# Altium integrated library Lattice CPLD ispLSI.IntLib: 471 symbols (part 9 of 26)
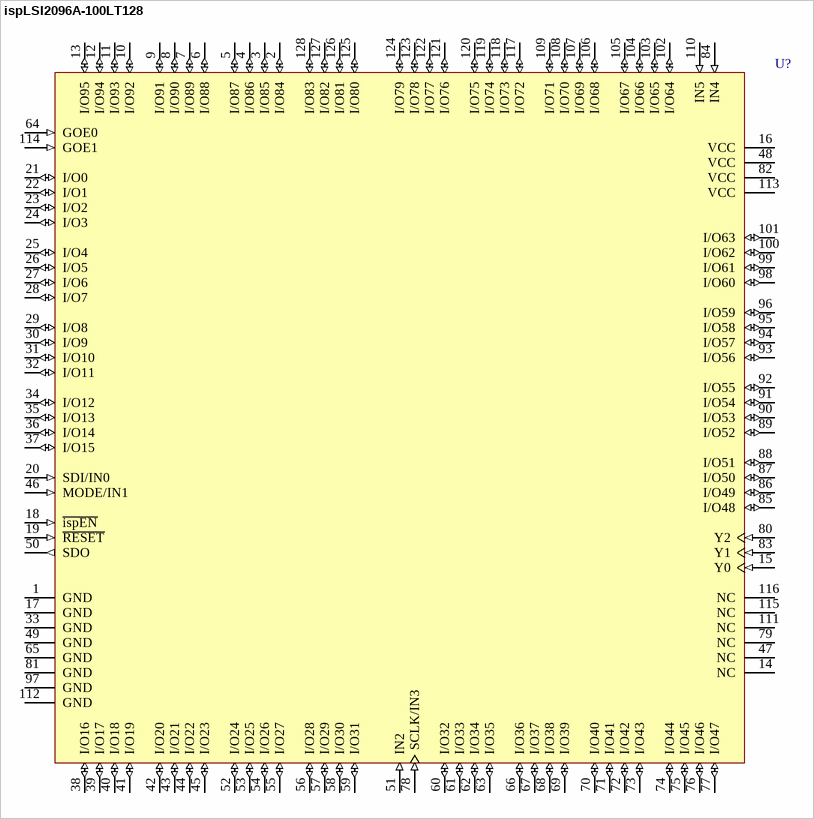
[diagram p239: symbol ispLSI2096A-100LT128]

## ispLSI2096A-100LT128
designator U?
In-System Programmable High-Density PLD; Note: Pins 20, 46 and 78 have dual function capability.
footprint TQFP128_N (Thin QFP, 128-Leads, Body 14x14mm, Pitch 0.4mm, IPC Medium Density)
footprint TQFP128_L (Thin QFP, 128-Leads, Body 14x14mm, Pitch 0.4mm, IPC High Density)
footprint TQFP128_M (Thin QFP, 128-Leads, Body 14x14mm, Pitch 0.4mm, IPC Low Density)
3D model 2096A-TQFP128 (128-Pin Thin Quad Flat Pack 0.4 mm Pitch)
pins: 1 GND (power), 2 I/O84 (io), 3 I/O85 (io), 4 I/O86 (io), 5 I/O87 (io), 6 I/O88 (io), 7 I/O89 (io), 8 I/O90 (io), 9 I/O91 (io), 10 I/O92 (io), 11 I/O93 (io), 12 I/O94 (io), 13 I/O95 (io), 14 NC, 15 Y0 (in), 16 VCC (power), 17 GND (power), 18 ~{ispEN} (in), 19 ~{RESET} (in), 20 SDI/IN0 (in), 21 I/O0 (io), 22 I/O1 (io), 23 I/O2 (io), 24 I/O3 (io), 25 I/O4 (io), 26 I/O5 (io), 27 I/O6 (io), 28 I/O7 (io), 29 I/O8 (io), 30 I/O9 (io), 31 I/O10 (io), 32 I/O11 (io), 33 GND (power), 34 I/O12 (io), 35 I/O13 (io), 36 I/O14 (io), 37 I/O15 (io), 38 I/O16 (io), 39 I/O17 (io), 40 I/O18 (io), 41 I/O19 (io), 42 I/O20 (io), 43 I/O21 (io), 44 I/O22 (io), 45 I/O23 (io), 46 MODE/IN1 (in), 47 NC, 48 VCC (power), 49 GND (power), 50 SDO (out), 51 IN2 (in), 52 I/O24 (io), 53 I/O25 (io), 54 I/O26 (io), 55 I/O27 (io), 56 I/O28 (io), 57 I/O29 (io), 58 I/O30 (io), 59 I/O31 (io), 60 I/O32 (io), 61 I/O33 (io), 62 I/O34 (io), 63 I/O35 (io), 64 GOE0 (in), 65 GND (power), 66 I/O36 (io), 67 I/O37 (io), 68 I/O38 (io), 69 I/O39 (io), 70 I/O40 (io), 71 I/O41 (io), 72 I/O42 (io), 73 I/O43 (io), 74 I/O44 (io), 75 I/O45 (io), 76 I/O46 (io), 77 I/O47 (io), 78 SCLK/IN3 (in), 79 NC, 80 Y2 (in), 81 GND (power), 82 VCC (power), 83 Y1 (in), 84 IN4 (in), 85 I/O48 (io), 86 I/O49 (io), 87 I/O50 (io), 88 I/O51 (io), 89 I/O52 (io), 90 I/O53 (io), 91 I/O54 (io), 92 I/O55 (io), 93 I/O56 (io), 94 I/O57 (io), 95 I/O58 (io), 96 I/O59 (io), 97 GND (power), 98 I/O60 (io), 99 I/O61 (io), 100 I/O62 (io), 101 I/O63 (io), 102 I/O64 (io), 103 I/O65 (io), 104 I/O66 (io), 105 I/O67 (io), 106 I/O68 (io), 107 I/O69 (io), 108 I/O70 (io), 109 I/O71 (io), 110 IN5 (in), 111 NC, 112 GND (power), 113 VCC (power), 114 GOE1 (in), 115 NC, 116 NC, 117 I/O72 (io), 118 I/O73 (io), 119 I/O74 (io), 120 I/O75 (io), 121 I/O76 (io), 122 I/O77 (io), 123 I/O78 (io), 124 I/O79 (io), 125 I/O80 (io), 126 I/O81 (io), 127 I/O82 (io), 128 I/O83 (io)

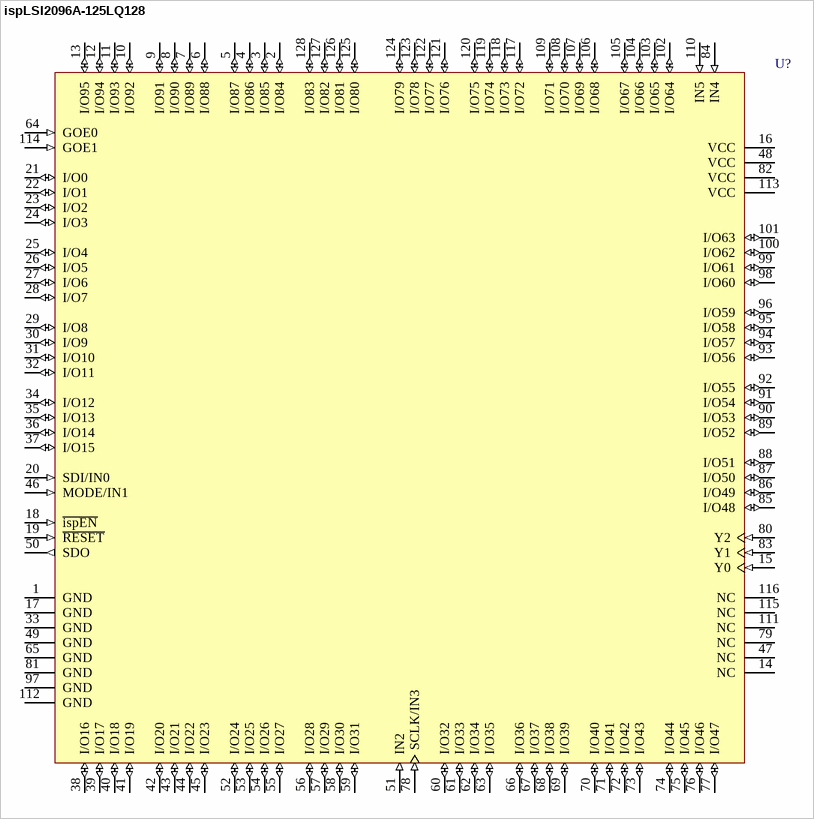
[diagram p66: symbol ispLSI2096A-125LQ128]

## ispLSI2096A-125LQ128
designator U?
In-System Programmable High-Density PLD; Note: Pins 20, 46 and 78 have dual function capability.
footprint PQFP128_N (QFP, 128-Leads, Body 28x28mm, Pitch 0.8mm, IPC Medium Density)
footprint PQFP128_L (QFP, 128-Leads, Body 28x28mm, Pitch 0.8mm, IPC High Density)
footprint PQFP128_M (QFP, 128-Leads, Body 28x28mm, Pitch 0.8mm, IPC Low Density)
3D model 2096A-PQFP128 (128-Pin Quad Flat Pack 0.8 mm Pitch)
pins: 1 GND (power), 2 I/O84 (io), 3 I/O85 (io), 4 I/O86 (io), 5 I/O87 (io), 6 I/O88 (io), 7 I/O89 (io), 8 I/O90 (io), 9 I/O91 (io), 10 I/O92 (io), 11 I/O93 (io), 12 I/O94 (io), 13 I/O95 (io), 14 NC, 15 Y0 (in), 16 VCC (power), 17 GND (power), 18 ~{ispEN} (in), 19 ~{RESET} (in), 20 SDI/IN0 (in), 21 I/O0 (io), 22 I/O1 (io), 23 I/O2 (io), 24 I/O3 (io), 25 I/O4 (io), 26 I/O5 (io), 27 I/O6 (io), 28 I/O7 (io), 29 I/O8 (io), 30 I/O9 (io), 31 I/O10 (io), 32 I/O11 (io), 33 GND (power), 34 I/O12 (io), 35 I/O13 (io), 36 I/O14 (io), 37 I/O15 (io), 38 I/O16 (io), 39 I/O17 (io), 40 I/O18 (io), 41 I/O19 (io), 42 I/O20 (io), 43 I/O21 (io), 44 I/O22 (io), 45 I/O23 (io), 46 MODE/IN1 (in), 47 NC, 48 VCC (power), 49 GND (power), 50 SDO (out), 51 IN2 (in), 52 I/O24 (io), 53 I/O25 (io), 54 I/O26 (io), 55 I/O27 (io), 56 I/O28 (io), 57 I/O29 (io), 58 I/O30 (io), 59 I/O31 (io), 60 I/O32 (io), 61 I/O33 (io), 62 I/O34 (io), 63 I/O35 (io), 64 GOE0 (in), 65 GND (power), 66 I/O36 (io), 67 I/O37 (io), 68 I/O38 (io), 69 I/O39 (io), 70 I/O40 (io), 71 I/O41 (io), 72 I/O42 (io), 73 I/O43 (io), 74 I/O44 (io), 75 I/O45 (io), 76 I/O46 (io), 77 I/O47 (io), 78 SCLK/IN3 (in), 79 NC, 80 Y2 (in), 81 GND (power), 82 VCC (power), 83 Y1 (in), 84 IN4 (in), 85 I/O48 (io), 86 I/O49 (io), 87 I/O50 (io), 88 I/O51 (io), 89 I/O52 (io), 90 I/O53 (io), 91 I/O54 (io), 92 I/O55 (io), 93 I/O56 (io), 94 I/O57 (io), 95 I/O58 (io), 96 I/O59 (io), 97 GND (power), 98 I/O60 (io), 99 I/O61 (io), 100 I/O62 (io), 101 I/O63 (io), 102 I/O64 (io), 103 I/O65 (io), 104 I/O66 (io), 105 I/O67 (io), 106 I/O68 (io), 107 I/O69 (io), 108 I/O70 (io), 109 I/O71 (io), 110 IN5 (in), 111 NC, 112 GND (power), 113 VCC (power), 114 GOE1 (in), 115 NC, 116 NC, 117 I/O72 (io), 118 I/O73 (io), 119 I/O74 (io), 120 I/O75 (io), 121 I/O76 (io), 122 I/O77 (io), 123 I/O78 (io), 124 I/O79 (io), 125 I/O80 (io), 126 I/O81 (io), 127 I/O82 (io), 128 I/O83 (io)

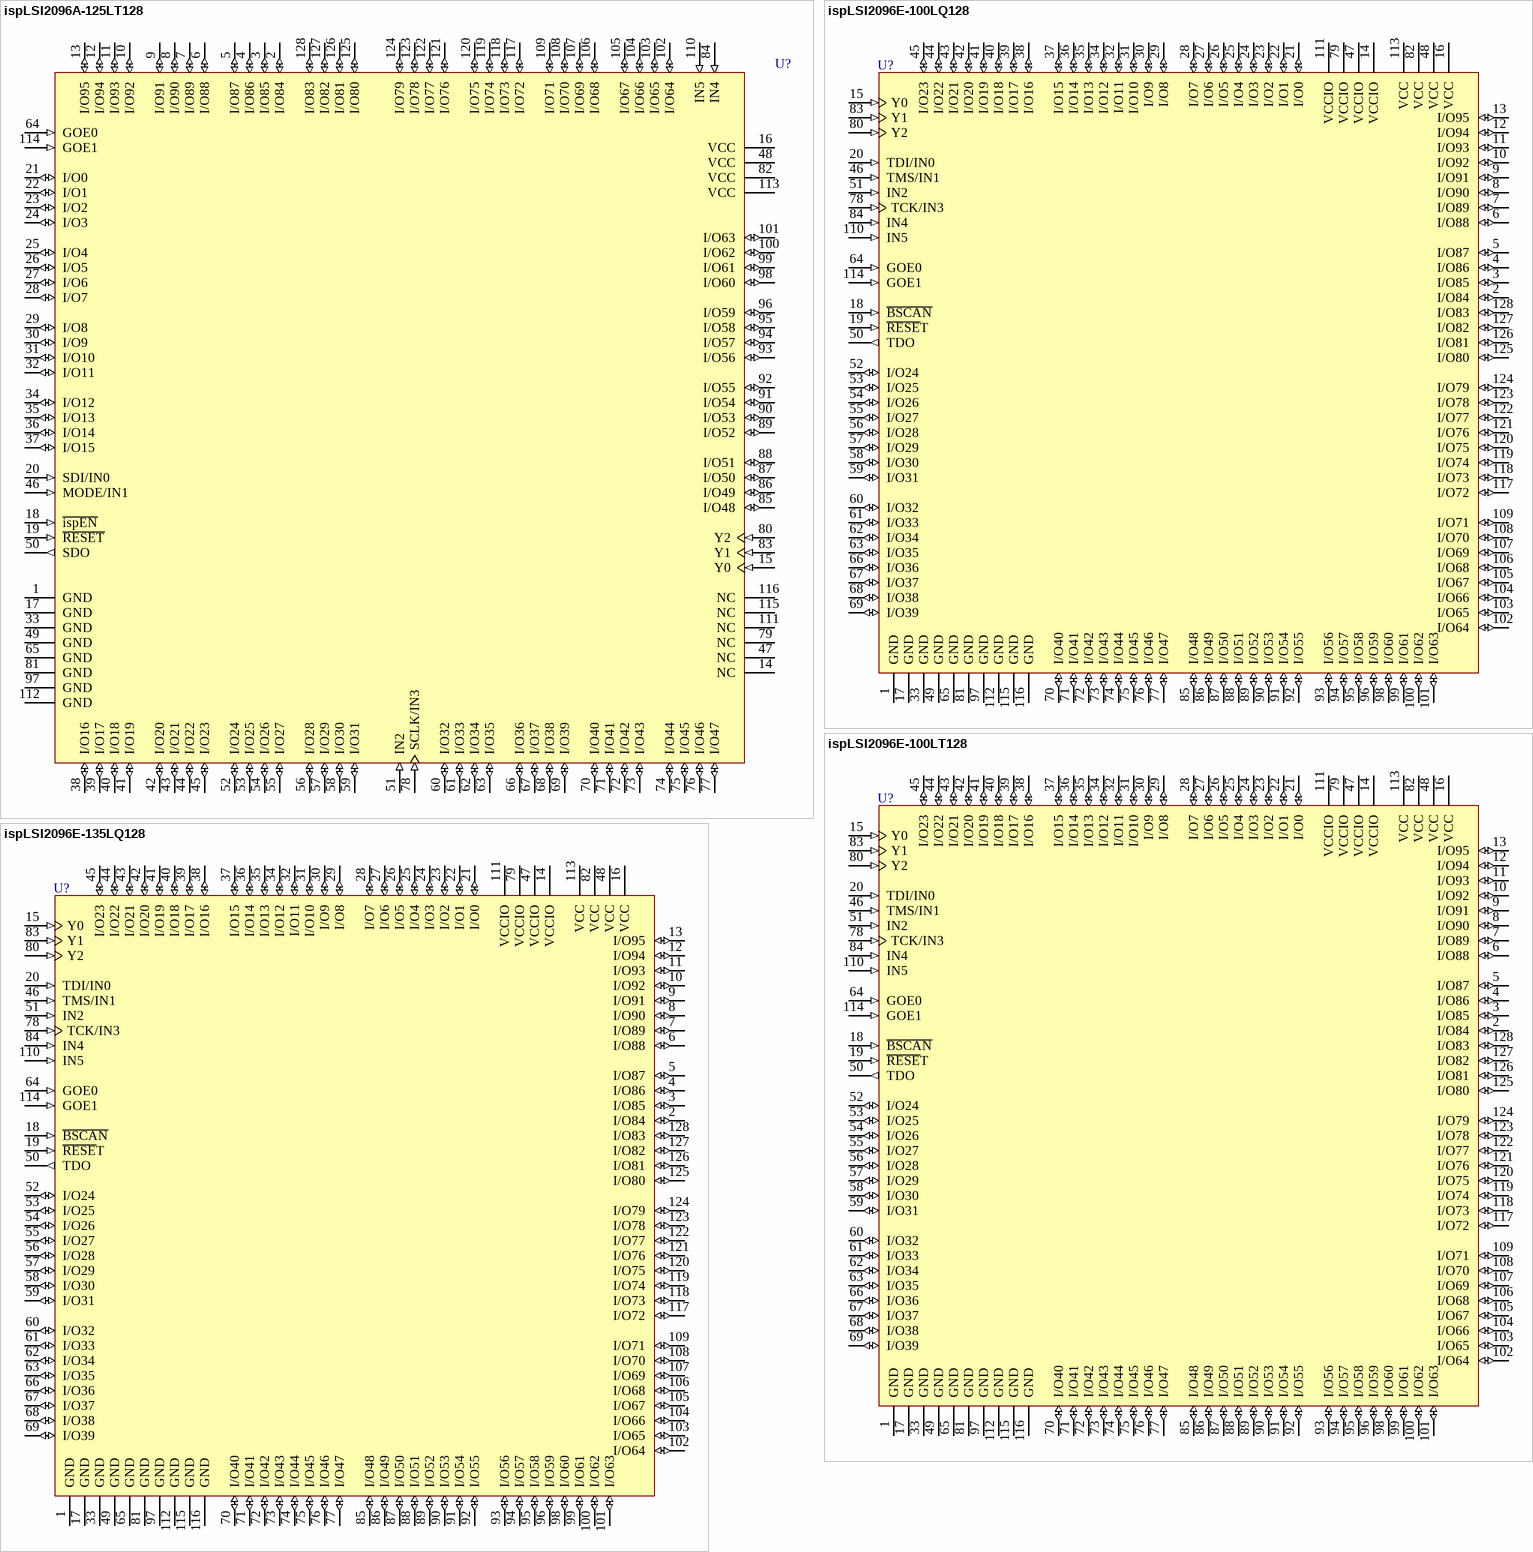
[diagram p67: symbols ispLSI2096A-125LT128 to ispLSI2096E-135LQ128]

## ispLSI2096A-125LT128
designator U?
In-System Programmable High-Density PLD; Note: Pins 20, 46 and 78 have dual function capability.
footprint TQFP128_N (Thin QFP, 128-Leads, Body 14x14mm, Pitch 0.4mm, IPC Medium Density)
footprint TQFP128_L (Thin QFP, 128-Leads, Body 14x14mm, Pitch 0.4mm, IPC High Density)
footprint TQFP128_M (Thin QFP, 128-Leads, Body 14x14mm, Pitch 0.4mm, IPC Low Density)
3D model 2096A-TQFP128 (128-Pin Thin Quad Flat Pack 0.4 mm Pitch)
pins: 1 GND (power), 2 I/O84 (io), 3 I/O85 (io), 4 I/O86 (io), 5 I/O87 (io), 6 I/O88 (io), 7 I/O89 (io), 8 I/O90 (io), 9 I/O91 (io), 10 I/O92 (io), 11 I/O93 (io), 12 I/O94 (io), 13 I/O95 (io), 14 NC, 15 Y0 (in), 16 VCC (power), 17 GND (power), 18 ~{ispEN} (in), 19 ~{RESET} (in), 20 SDI/IN0 (in), 21 I/O0 (io), 22 I/O1 (io), 23 I/O2 (io), 24 I/O3 (io), 25 I/O4 (io), 26 I/O5 (io), 27 I/O6 (io), 28 I/O7 (io), 29 I/O8 (io), 30 I/O9 (io), 31 I/O10 (io), 32 I/O11 (io), 33 GND (power), 34 I/O12 (io), 35 I/O13 (io), 36 I/O14 (io), 37 I/O15 (io), 38 I/O16 (io), 39 I/O17 (io), 40 I/O18 (io), 41 I/O19 (io), 42 I/O20 (io), 43 I/O21 (io), 44 I/O22 (io), 45 I/O23 (io), 46 MODE/IN1 (in), 47 NC, 48 VCC (power), 49 GND (power), 50 SDO (out), 51 IN2 (in), 52 I/O24 (io), 53 I/O25 (io), 54 I/O26 (io), 55 I/O27 (io), 56 I/O28 (io), 57 I/O29 (io), 58 I/O30 (io), 59 I/O31 (io), 60 I/O32 (io), 61 I/O33 (io), 62 I/O34 (io), 63 I/O35 (io), 64 GOE0 (in), 65 GND (power), 66 I/O36 (io), 67 I/O37 (io), 68 I/O38 (io), 69 I/O39 (io), 70 I/O40 (io), 71 I/O41 (io), 72 I/O42 (io), 73 I/O43 (io), 74 I/O44 (io), 75 I/O45 (io), 76 I/O46 (io), 77 I/O47 (io), 78 SCLK/IN3 (in), 79 NC, 80 Y2 (in), 81 GND (power), 82 VCC (power), 83 Y1 (in), 84 IN4 (in), 85 I/O48 (io), 86 I/O49 (io), 87 I/O50 (io), 88 I/O51 (io), 89 I/O52 (io), 90 I/O53 (io), 91 I/O54 (io), 92 I/O55 (io), 93 I/O56 (io), 94 I/O57 (io), 95 I/O58 (io), 96 I/O59 (io), 97 GND (power), 98 I/O60 (io), 99 I/O61 (io), 100 I/O62 (io), 101 I/O63 (io), 102 I/O64 (io), 103 I/O65 (io), 104 I/O66 (io), 105 I/O67 (io), 106 I/O68 (io), 107 I/O69 (io), 108 I/O70 (io), 109 I/O71 (io), 110 IN5 (in), 111 NC, 112 GND (power), 113 VCC (power), 114 GOE1 (in), 115 NC, 116 NC, 117 I/O72 (io), 118 I/O73 (io), 119 I/O74 (io), 120 I/O75 (io), 121 I/O76 (io), 122 I/O77 (io), 123 I/O78 (io), 124 I/O79 (io), 125 I/O80 (io), 126 I/O81 (io), 127 I/O82 (io), 128 I/O83 (io)

## ispLSI2096E-100LQ128
designator U?
In-System Programmable SuperFAST High Density PLD
footprint PQFP128_N (QFP, 128-Leads, Body 28x28mm, Pitch 0.8mm, IPC Medium Density)
footprint PQFP128_L (QFP, 128-Leads, Body 28x28mm, Pitch 0.8mm, IPC High Density)
footprint PQFP128_M (QFP, 128-Leads, Body 28x28mm, Pitch 0.8mm, IPC Low Density)
3D model 2096E-PQFP128 (128-Pin Quad Flat Pack 0.8 mm Pitch)
pins: 1 GND (power), 2 I/O84 (io), 3 I/O85 (io), 4 I/O86 (io), 5 I/O87 (io), 6 I/O88 (io), 7 I/O89 (io), 8 I/O90 (io), 9 I/O91 (io), 10 I/O92 (io), 11 I/O93 (io), 12 I/O94 (io), 13 I/O95 (io), 14 VCCIO (power), 15 Y0 (in), 16 VCC (power), 17 GND (power), 18 ~{BSCAN} (in), 19 ~{RESE}T (in), 20 TDI/IN0 (in), 21 I/O0 (io), 22 I/O1 (io), 23 I/O2 (io), 24 I/O3 (io), 25 I/O4 (io), 26 I/O5 (io), 27 I/O6 (io), 28 I/O7 (io), 29 I/O8 (io), 30 I/O9 (io), 31 I/O10 (io), 32 I/O11 (io), 33 GND (power), 34 I/O12 (io), 35 I/O13 (io), 36 I/O14 (io), 37 I/O15 (io), 38 I/O16 (io), 39 I/O17 (io), 40 I/O18 (io), 41 I/O19 (io), 42 I/O20 (io), 43 I/O21 (io), 44 I/O22 (io), 45 I/O23 (io), 46 TMS/IN1 (in), 47 VCCIO (power), 48 VCC (power), 49 GND (power), 50 TDO (out), 51 IN2 (in), 52 I/O24 (io), 53 I/O25 (io), 54 I/O26 (io), 55 I/O27 (io), 56 I/O28 (io), 57 I/O29 (io), 58 I/O30 (io), 59 I/O31 (io), 60 I/O32 (io), 61 I/O33 (io), 62 I/O34 (io), 63 I/O35 (io), 64 GOE0 (in), 65 GND (power), 66 I/O36 (io), 67 I/O37 (io), 68 I/O38 (io), 69 I/O39 (io), 70 I/O40 (io), 71 I/O41 (io), 72 I/O42 (io), 73 I/O43 (io), 74 I/O44 (io), 75 I/O45 (io), 76 I/O46 (io), 77 I/O47 (io), 78 TCK/IN3 (in), 79 VCCIO (power), 80 Y2 (in), 81 GND (power), 82 VCC (power), 83 Y1 (in), 84 IN4 (in), 85 I/O48 (io), 86 I/O49 (io), 87 I/O50 (io), 88 I/O51 (io), 89 I/O52 (io), 90 I/O53 (io), 91 I/O54 (io), 92 I/O55 (io), 93 I/O56 (io), 94 I/O57 (io), 95 I/O58 (io), 96 I/O59 (io), 97 GND (power), 98 I/O60 (io), 99 I/O61 (io), 100 I/O62 (io), 101 I/O63 (io), 102 I/O64 (io), 103 I/O65 (io), 104 I/O66 (io), 105 I/O67 (io), 106 I/O68 (io), 107 I/O69 (io), 108 I/O70 (io), 109 I/O71 (io), 110 IN5 (in), 111 VCCIO (power), 112 GND (power), 113 VCC (power), 114 GOE1 (in), 115 GND (power), 116 GND (power), 117 I/O72 (io), 118 I/O73 (io), 119 I/O74 (io), 120 I/O75 (io), 121 I/O76 (io), 122 I/O77 (io), 123 I/O78 (io), 124 I/O79 (io), 125 I/O80 (io), 126 I/O81 (io), 127 I/O82 (io), 128 I/O83 (io)

## ispLSI2096E-100LT128
designator U?
In-System Programmable SuperFAST High Density PLD
footprint TQFP128_N (Thin QFP, 128-Leads, Body 14x14mm, Pitch 0.4mm, IPC Medium Density)
footprint TQFP128_L (Thin QFP, 128-Leads, Body 14x14mm, Pitch 0.4mm, IPC High Density)
footprint TQFP128_M (Thin QFP, 128-Leads, Body 14x14mm, Pitch 0.4mm, IPC Low Density)
3D model 2096E-TQFP128 (128-Pin Thin Quad Flat Pack 0.4 mm Pitch)
pins: 1 GND (power), 2 I/O84 (io), 3 I/O85 (io), 4 I/O86 (io), 5 I/O87 (io), 6 I/O88 (io), 7 I/O89 (io), 8 I/O90 (io), 9 I/O91 (io), 10 I/O92 (io), 11 I/O93 (io), 12 I/O94 (io), 13 I/O95 (io), 14 VCCIO (power), 15 Y0 (in), 16 VCC (power), 17 GND (power), 18 ~{BSCAN} (in), 19 ~{RESE}T (in), 20 TDI/IN0 (in), 21 I/O0 (io), 22 I/O1 (io), 23 I/O2 (io), 24 I/O3 (io), 25 I/O4 (io), 26 I/O5 (io), 27 I/O6 (io), 28 I/O7 (io), 29 I/O8 (io), 30 I/O9 (io), 31 I/O10 (io), 32 I/O11 (io), 33 GND (power), 34 I/O12 (io), 35 I/O13 (io), 36 I/O14 (io), 37 I/O15 (io), 38 I/O16 (io), 39 I/O17 (io), 40 I/O18 (io), 41 I/O19 (io), 42 I/O20 (io), 43 I/O21 (io), 44 I/O22 (io), 45 I/O23 (io), 46 TMS/IN1 (in), 47 VCCIO (power), 48 VCC (power), 49 GND (power), 50 TDO (out), 51 IN2 (in), 52 I/O24 (io), 53 I/O25 (io), 54 I/O26 (io), 55 I/O27 (io), 56 I/O28 (io), 57 I/O29 (io), 58 I/O30 (io), 59 I/O31 (io), 60 I/O32 (io), 61 I/O33 (io), 62 I/O34 (io), 63 I/O35 (io), 64 GOE0 (in), 65 GND (power), 66 I/O36 (io), 67 I/O37 (io), 68 I/O38 (io), 69 I/O39 (io), 70 I/O40 (io), 71 I/O41 (io), 72 I/O42 (io), 73 I/O43 (io), 74 I/O44 (io), 75 I/O45 (io), 76 I/O46 (io), 77 I/O47 (io), 78 TCK/IN3 (in), 79 VCCIO (power), 80 Y2 (in), 81 GND (power), 82 VCC (power), 83 Y1 (in), 84 IN4 (in), 85 I/O48 (io), 86 I/O49 (io), 87 I/O50 (io), 88 I/O51 (io), 89 I/O52 (io), 90 I/O53 (io), 91 I/O54 (io), 92 I/O55 (io), 93 I/O56 (io), 94 I/O57 (io), 95 I/O58 (io), 96 I/O59 (io), 97 GND (power), 98 I/O60 (io), 99 I/O61 (io), 100 I/O62 (io), 101 I/O63 (io), 102 I/O64 (io), 103 I/O65 (io), 104 I/O66 (io), 105 I/O67 (io), 106 I/O68 (io), 107 I/O69 (io), 108 I/O70 (io), 109 I/O71 (io), 110 IN5 (in), 111 VCCIO (power), 112 GND (power), 113 VCC (power), 114 GOE1 (in), 115 GND (power), 116 GND (power), 117 I/O72 (io), 118 I/O73 (io), 119 I/O74 (io), 120 I/O75 (io), 121 I/O76 (io), 122 I/O77 (io), 123 I/O78 (io), 124 I/O79 (io), 125 I/O80 (io), 126 I/O81 (io), 127 I/O82 (io), 128 I/O83 (io)

## ispLSI2096E-135LQ128
designator U?
In-System Programmable SuperFAST High Density PLD
footprint PQFP128_N (QFP, 128-Leads, Body 28x28mm, Pitch 0.8mm, IPC Medium Density)
footprint PQFP128_L (QFP, 128-Leads, Body 28x28mm, Pitch 0.8mm, IPC High Density)
footprint PQFP128_M (QFP, 128-Leads, Body 28x28mm, Pitch 0.8mm, IPC Low Density)
3D model 2096E-PQFP128 (128-Pin Quad Flat Pack 0.8 mm Pitch)
pins: 1 GND (power), 2 I/O84 (io), 3 I/O85 (io), 4 I/O86 (io), 5 I/O87 (io), 6 I/O88 (io), 7 I/O89 (io), 8 I/O90 (io), 9 I/O91 (io), 10 I/O92 (io), 11 I/O93 (io), 12 I/O94 (io), 13 I/O95 (io), 14 VCCIO (power), 15 Y0 (in), 16 VCC (power), 17 GND (power), 18 ~{BSCAN} (in), 19 ~{RESE}T (in), 20 TDI/IN0 (in), 21 I/O0 (io), 22 I/O1 (io), 23 I/O2 (io), 24 I/O3 (io), 25 I/O4 (io), 26 I/O5 (io), 27 I/O6 (io), 28 I/O7 (io), 29 I/O8 (io), 30 I/O9 (io), 31 I/O10 (io), 32 I/O11 (io), 33 GND (power), 34 I/O12 (io), 35 I/O13 (io), 36 I/O14 (io), 37 I/O15 (io), 38 I/O16 (io), 39 I/O17 (io), 40 I/O18 (io), 41 I/O19 (io), 42 I/O20 (io), 43 I/O21 (io), 44 I/O22 (io), 45 I/O23 (io), 46 TMS/IN1 (in), 47 VCCIO (power), 48 VCC (power), 49 GND (power), 50 TDO (out), 51 IN2 (in), 52 I/O24 (io), 53 I/O25 (io), 54 I/O26 (io), 55 I/O27 (io), 56 I/O28 (io), 57 I/O29 (io), 58 I/O30 (io), 59 I/O31 (io), 60 I/O32 (io), 61 I/O33 (io), 62 I/O34 (io), 63 I/O35 (io), 64 GOE0 (in), 65 GND (power), 66 I/O36 (io), 67 I/O37 (io), 68 I/O38 (io), 69 I/O39 (io), 70 I/O40 (io), 71 I/O41 (io), 72 I/O42 (io), 73 I/O43 (io), 74 I/O44 (io), 75 I/O45 (io), 76 I/O46 (io), 77 I/O47 (io), 78 TCK/IN3 (in), 79 VCCIO (power), 80 Y2 (in), 81 GND (power), 82 VCC (power), 83 Y1 (in), 84 IN4 (in), 85 I/O48 (io), 86 I/O49 (io), 87 I/O50 (io), 88 I/O51 (io), 89 I/O52 (io), 90 I/O53 (io), 91 I/O54 (io), 92 I/O55 (io), 93 I/O56 (io), 94 I/O57 (io), 95 I/O58 (io), 96 I/O59 (io), 97 GND (power), 98 I/O60 (io), 99 I/O61 (io), 100 I/O62 (io), 101 I/O63 (io), 102 I/O64 (io), 103 I/O65 (io), 104 I/O66 (io), 105 I/O67 (io), 106 I/O68 (io), 107 I/O69 (io), 108 I/O70 (io), 109 I/O71 (io), 110 IN5 (in), 111 VCCIO (power), 112 GND (power), 113 VCC (power), 114 GOE1 (in), 115 GND (power), 116 GND (power), 117 I/O72 (io), 118 I/O73 (io), 119 I/O74 (io), 120 I/O75 (io), 121 I/O76 (io), 122 I/O77 (io), 123 I/O78 (io), 124 I/O79 (io), 125 I/O80 (io), 126 I/O81 (io), 127 I/O82 (io), 128 I/O83 (io)

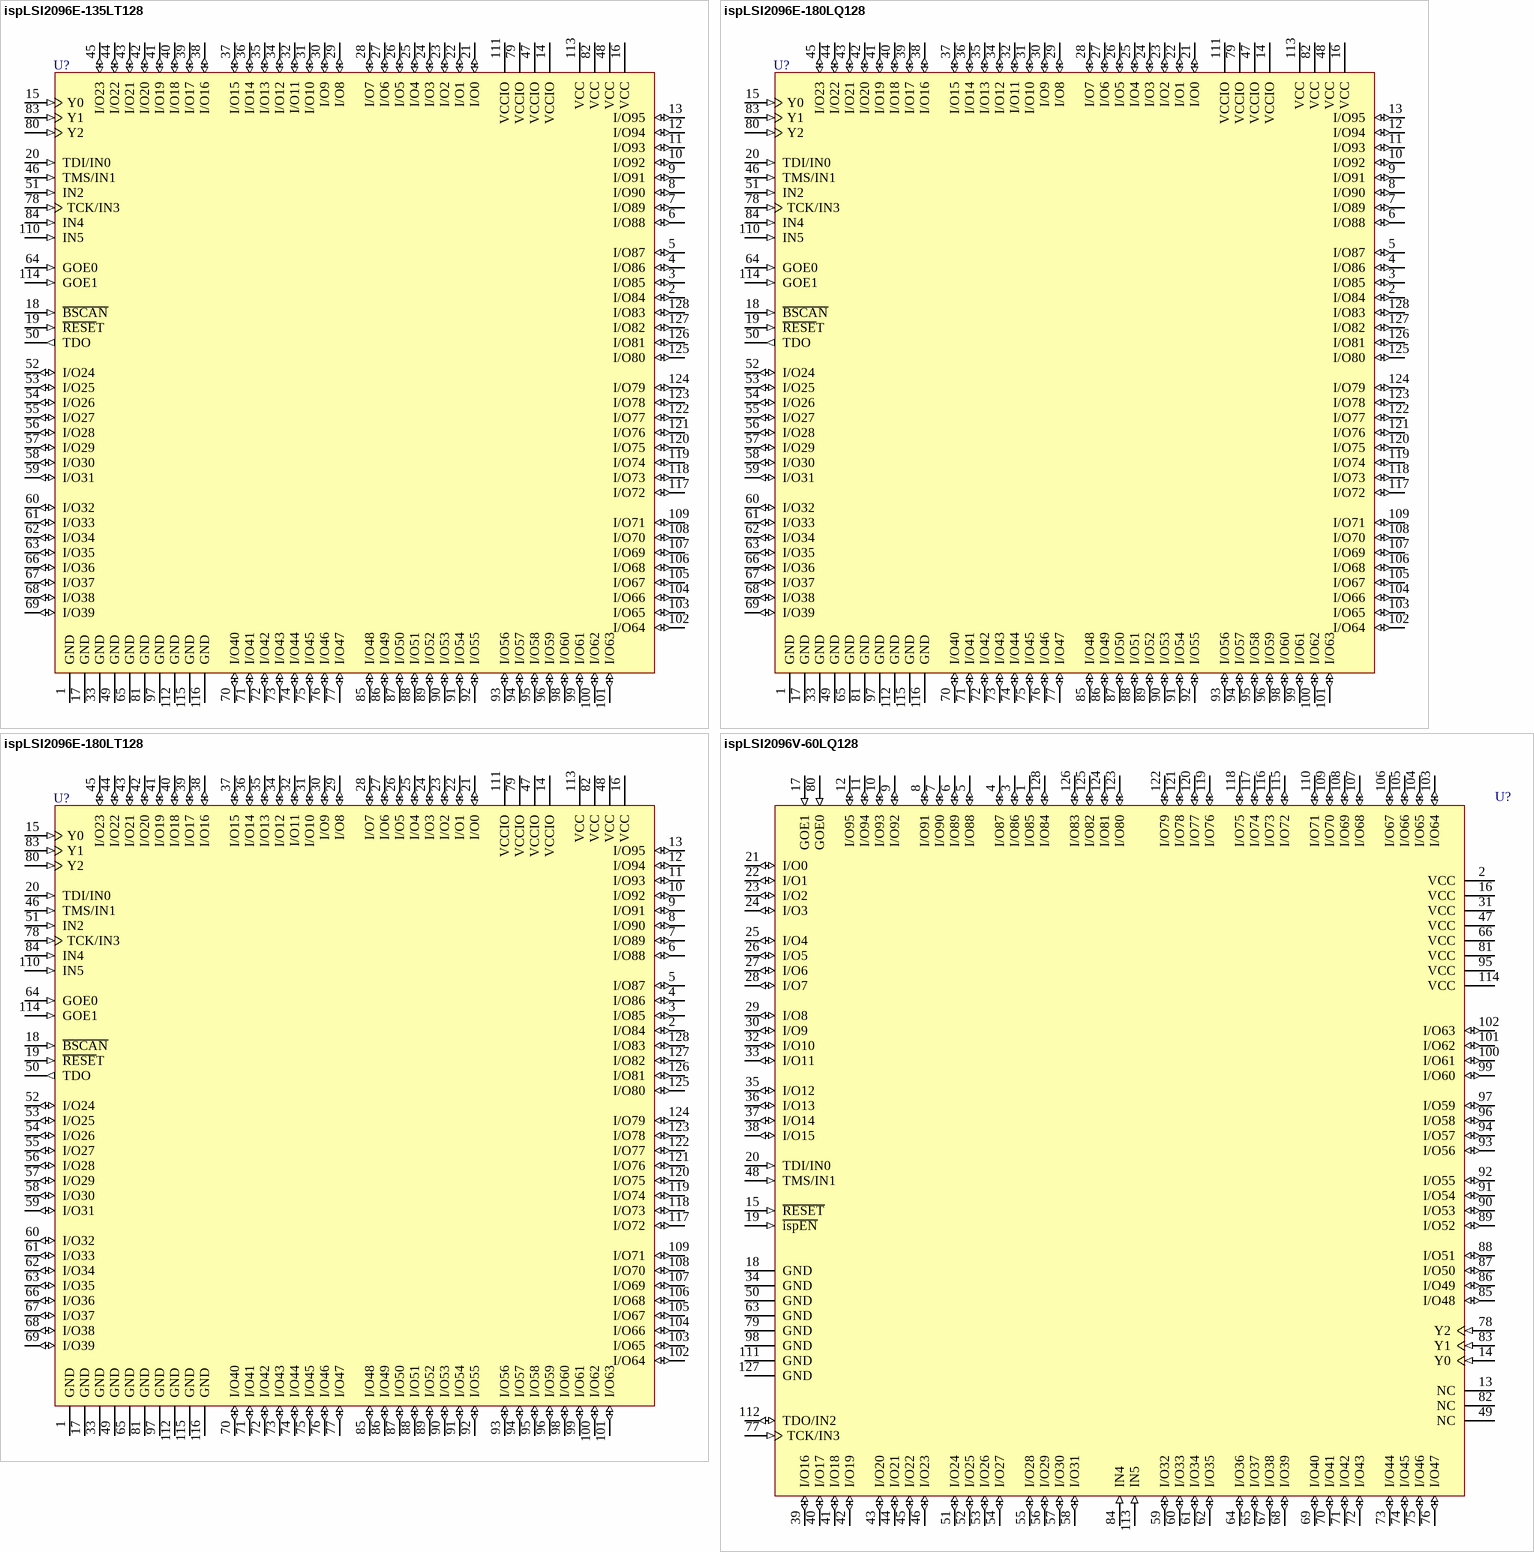
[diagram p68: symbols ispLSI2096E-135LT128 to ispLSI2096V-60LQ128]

## ispLSI2096E-135LT128
designator U?
In-System Programmable SuperFAST High Density PLD
footprint TQFP128_N (Thin QFP, 128-Leads, Body 14x14mm, Pitch 0.4mm, IPC Medium Density)
footprint TQFP128_L (Thin QFP, 128-Leads, Body 14x14mm, Pitch 0.4mm, IPC High Density)
footprint TQFP128_M (Thin QFP, 128-Leads, Body 14x14mm, Pitch 0.4mm, IPC Low Density)
3D model 2096E-TQFP128 (128-Pin Thin Quad Flat Pack 0.4 mm Pitch)
pins: 1 GND (power), 2 I/O84 (io), 3 I/O85 (io), 4 I/O86 (io), 5 I/O87 (io), 6 I/O88 (io), 7 I/O89 (io), 8 I/O90 (io), 9 I/O91 (io), 10 I/O92 (io), 11 I/O93 (io), 12 I/O94 (io), 13 I/O95 (io), 14 VCCIO (power), 15 Y0 (in), 16 VCC (power), 17 GND (power), 18 ~{BSCAN} (in), 19 ~{RESE}T (in), 20 TDI/IN0 (in), 21 I/O0 (io), 22 I/O1 (io), 23 I/O2 (io), 24 I/O3 (io), 25 I/O4 (io), 26 I/O5 (io), 27 I/O6 (io), 28 I/O7 (io), 29 I/O8 (io), 30 I/O9 (io), 31 I/O10 (io), 32 I/O11 (io), 33 GND (power), 34 I/O12 (io), 35 I/O13 (io), 36 I/O14 (io), 37 I/O15 (io), 38 I/O16 (io), 39 I/O17 (io), 40 I/O18 (io), 41 I/O19 (io), 42 I/O20 (io), 43 I/O21 (io), 44 I/O22 (io), 45 I/O23 (io), 46 TMS/IN1 (in), 47 VCCIO (power), 48 VCC (power), 49 GND (power), 50 TDO (out), 51 IN2 (in), 52 I/O24 (io), 53 I/O25 (io), 54 I/O26 (io), 55 I/O27 (io), 56 I/O28 (io), 57 I/O29 (io), 58 I/O30 (io), 59 I/O31 (io), 60 I/O32 (io), 61 I/O33 (io), 62 I/O34 (io), 63 I/O35 (io), 64 GOE0 (in), 65 GND (power), 66 I/O36 (io), 67 I/O37 (io), 68 I/O38 (io), 69 I/O39 (io), 70 I/O40 (io), 71 I/O41 (io), 72 I/O42 (io), 73 I/O43 (io), 74 I/O44 (io), 75 I/O45 (io), 76 I/O46 (io), 77 I/O47 (io), 78 TCK/IN3 (in), 79 VCCIO (power), 80 Y2 (in), 81 GND (power), 82 VCC (power), 83 Y1 (in), 84 IN4 (in), 85 I/O48 (io), 86 I/O49 (io), 87 I/O50 (io), 88 I/O51 (io), 89 I/O52 (io), 90 I/O53 (io), 91 I/O54 (io), 92 I/O55 (io), 93 I/O56 (io), 94 I/O57 (io), 95 I/O58 (io), 96 I/O59 (io), 97 GND (power), 98 I/O60 (io), 99 I/O61 (io), 100 I/O62 (io), 101 I/O63 (io), 102 I/O64 (io), 103 I/O65 (io), 104 I/O66 (io), 105 I/O67 (io), 106 I/O68 (io), 107 I/O69 (io), 108 I/O70 (io), 109 I/O71 (io), 110 IN5 (in), 111 VCCIO (power), 112 GND (power), 113 VCC (power), 114 GOE1 (in), 115 GND (power), 116 GND (power), 117 I/O72 (io), 118 I/O73 (io), 119 I/O74 (io), 120 I/O75 (io), 121 I/O76 (io), 122 I/O77 (io), 123 I/O78 (io), 124 I/O79 (io), 125 I/O80 (io), 126 I/O81 (io), 127 I/O82 (io), 128 I/O83 (io)

## ispLSI2096E-180LQ128
designator U?
In-System Programmable SuperFAST High Density PLD
footprint PQFP128_N (QFP, 128-Leads, Body 28x28mm, Pitch 0.8mm, IPC Medium Density)
footprint PQFP128_L (QFP, 128-Leads, Body 28x28mm, Pitch 0.8mm, IPC High Density)
footprint PQFP128_M (QFP, 128-Leads, Body 28x28mm, Pitch 0.8mm, IPC Low Density)
3D model 2096E-PQFP128 (128-Pin Quad Flat Pack 0.8 mm Pitch)
pins: 1 GND (power), 2 I/O84 (io), 3 I/O85 (io), 4 I/O86 (io), 5 I/O87 (io), 6 I/O88 (io), 7 I/O89 (io), 8 I/O90 (io), 9 I/O91 (io), 10 I/O92 (io), 11 I/O93 (io), 12 I/O94 (io), 13 I/O95 (io), 14 VCCIO (power), 15 Y0 (in), 16 VCC (power), 17 GND (power), 18 ~{BSCAN} (in), 19 ~{RESE}T (in), 20 TDI/IN0 (in), 21 I/O0 (io), 22 I/O1 (io), 23 I/O2 (io), 24 I/O3 (io), 25 I/O4 (io), 26 I/O5 (io), 27 I/O6 (io), 28 I/O7 (io), 29 I/O8 (io), 30 I/O9 (io), 31 I/O10 (io), 32 I/O11 (io), 33 GND (power), 34 I/O12 (io), 35 I/O13 (io), 36 I/O14 (io), 37 I/O15 (io), 38 I/O16 (io), 39 I/O17 (io), 40 I/O18 (io), 41 I/O19 (io), 42 I/O20 (io), 43 I/O21 (io), 44 I/O22 (io), 45 I/O23 (io), 46 TMS/IN1 (in), 47 VCCIO (power), 48 VCC (power), 49 GND (power), 50 TDO (out), 51 IN2 (in), 52 I/O24 (io), 53 I/O25 (io), 54 I/O26 (io), 55 I/O27 (io), 56 I/O28 (io), 57 I/O29 (io), 58 I/O30 (io), 59 I/O31 (io), 60 I/O32 (io), 61 I/O33 (io), 62 I/O34 (io), 63 I/O35 (io), 64 GOE0 (in), 65 GND (power), 66 I/O36 (io), 67 I/O37 (io), 68 I/O38 (io), 69 I/O39 (io), 70 I/O40 (io), 71 I/O41 (io), 72 I/O42 (io), 73 I/O43 (io), 74 I/O44 (io), 75 I/O45 (io), 76 I/O46 (io), 77 I/O47 (io), 78 TCK/IN3 (in), 79 VCCIO (power), 80 Y2 (in), 81 GND (power), 82 VCC (power), 83 Y1 (in), 84 IN4 (in), 85 I/O48 (io), 86 I/O49 (io), 87 I/O50 (io), 88 I/O51 (io), 89 I/O52 (io), 90 I/O53 (io), 91 I/O54 (io), 92 I/O55 (io), 93 I/O56 (io), 94 I/O57 (io), 95 I/O58 (io), 96 I/O59 (io), 97 GND (power), 98 I/O60 (io), 99 I/O61 (io), 100 I/O62 (io), 101 I/O63 (io), 102 I/O64 (io), 103 I/O65 (io), 104 I/O66 (io), 105 I/O67 (io), 106 I/O68 (io), 107 I/O69 (io), 108 I/O70 (io), 109 I/O71 (io), 110 IN5 (in), 111 VCCIO (power), 112 GND (power), 113 VCC (power), 114 GOE1 (in), 115 GND (power), 116 GND (power), 117 I/O72 (io), 118 I/O73 (io), 119 I/O74 (io), 120 I/O75 (io), 121 I/O76 (io), 122 I/O77 (io), 123 I/O78 (io), 124 I/O79 (io), 125 I/O80 (io), 126 I/O81 (io), 127 I/O82 (io), 128 I/O83 (io)

## ispLSI2096E-180LT128
designator U?
In-System Programmable SuperFAST High Density PLD
footprint TQFP128_N (Thin QFP, 128-Leads, Body 14x14mm, Pitch 0.4mm, IPC Medium Density)
footprint TQFP128_L (Thin QFP, 128-Leads, Body 14x14mm, Pitch 0.4mm, IPC High Density)
footprint TQFP128_M (Thin QFP, 128-Leads, Body 14x14mm, Pitch 0.4mm, IPC Low Density)
3D model 2096E-TQFP128 (128-Pin Thin Quad Flat Pack 0.4 mm Pitch)
pins: 1 GND (power), 2 I/O84 (io), 3 I/O85 (io), 4 I/O86 (io), 5 I/O87 (io), 6 I/O88 (io), 7 I/O89 (io), 8 I/O90 (io), 9 I/O91 (io), 10 I/O92 (io), 11 I/O93 (io), 12 I/O94 (io), 13 I/O95 (io), 14 VCCIO (power), 15 Y0 (in), 16 VCC (power), 17 GND (power), 18 ~{BSCAN} (in), 19 ~{RESE}T (in), 20 TDI/IN0 (in), 21 I/O0 (io), 22 I/O1 (io), 23 I/O2 (io), 24 I/O3 (io), 25 I/O4 (io), 26 I/O5 (io), 27 I/O6 (io), 28 I/O7 (io), 29 I/O8 (io), 30 I/O9 (io), 31 I/O10 (io), 32 I/O11 (io), 33 GND (power), 34 I/O12 (io), 35 I/O13 (io), 36 I/O14 (io), 37 I/O15 (io), 38 I/O16 (io), 39 I/O17 (io), 40 I/O18 (io), 41 I/O19 (io), 42 I/O20 (io), 43 I/O21 (io), 44 I/O22 (io), 45 I/O23 (io), 46 TMS/IN1 (in), 47 VCCIO (power), 48 VCC (power), 49 GND (power), 50 TDO (out), 51 IN2 (in), 52 I/O24 (io), 53 I/O25 (io), 54 I/O26 (io), 55 I/O27 (io), 56 I/O28 (io), 57 I/O29 (io), 58 I/O30 (io), 59 I/O31 (io), 60 I/O32 (io), 61 I/O33 (io), 62 I/O34 (io), 63 I/O35 (io), 64 GOE0 (in), 65 GND (power), 66 I/O36 (io), 67 I/O37 (io), 68 I/O38 (io), 69 I/O39 (io), 70 I/O40 (io), 71 I/O41 (io), 72 I/O42 (io), 73 I/O43 (io), 74 I/O44 (io), 75 I/O45 (io), 76 I/O46 (io), 77 I/O47 (io), 78 TCK/IN3 (in), 79 VCCIO (power), 80 Y2 (in), 81 GND (power), 82 VCC (power), 83 Y1 (in), 84 IN4 (in), 85 I/O48 (io), 86 I/O49 (io), 87 I/O50 (io), 88 I/O51 (io), 89 I/O52 (io), 90 I/O53 (io), 91 I/O54 (io), 92 I/O55 (io), 93 I/O56 (io), 94 I/O57 (io), 95 I/O58 (io), 96 I/O59 (io), 97 GND (power), 98 I/O60 (io), 99 I/O61 (io), 100 I/O62 (io), 101 I/O63 (io), 102 I/O64 (io), 103 I/O65 (io), 104 I/O66 (io), 105 I/O67 (io), 106 I/O68 (io), 107 I/O69 (io), 108 I/O70 (io), 109 I/O71 (io), 110 IN5 (in), 111 VCCIO (power), 112 GND (power), 113 VCC (power), 114 GOE1 (in), 115 GND (power), 116 GND (power), 117 I/O72 (io), 118 I/O73 (io), 119 I/O74 (io), 120 I/O75 (io), 121 I/O76 (io), 122 I/O77 (io), 123 I/O78 (io), 124 I/O79 (io), 125 I/O80 (io), 126 I/O81 (io), 127 I/O82 (io), 128 I/O83 (io)

## ispLSI2096V-60LQ128
designator U?
3.3V High-Density Programmable Logic
footprint PQFP128_N (QFP, 128-Leads, Body 28x28mm, Pitch 0.8mm, IPC Medium Density)
footprint PQFP128_L (QFP, 128-Leads, Body 28x28mm, Pitch 0.8mm, IPC High Density)
footprint PQFP128_M (QFP, 128-Leads, Body 28x28mm, Pitch 0.8mm, IPC Low Density)
3D model 2096V-PQFP128 (128-Pin Quad Flat Pack 0.8 mm Pitch)
pins: 1 I/O85 (io), 2 VCC (power), 3 I/O86 (io), 4 I/O87 (io), 5 I/O88 (io), 6 I/O89 (io), 7 I/O90 (io), 8 I/O91 (io), 9 I/O92 (io), 10 I/O93 (io), 11 I/O94 (io), 12 I/O95 (io), 13 NC, 14 Y0 (in), 15 ~{RESET} (in), 16 VCC (power), 17 GOE1 (in), 18 GND (power), 19 ~{ispEN} (in), 20 TDI/IN0 (in), 21 I/O0 (io), 22 I/O1 (io), 23 I/O2 (io), 24 I/O3 (io), 25 I/O4 (io), 26 I/O5 (io), 27 I/O6 (io), 28 I/O7 (io), 29 I/O8 (io), 30 I/O9 (io), 31 VCC (power), 32 I/O10 (io), 33 I/O11 (io), 34 GND (power), 35 I/O12 (io), 36 I/O13 (io), 37 I/O14 (io), 38 I/O15 (io), 39 I/O16 (io), 40 I/O17 (io), 41 I/O18 (io), 42 I/O19 (io), 43 I/O20 (io), 44 I/O21 (io), 45 I/O22 (io), 46 I/O23 (io), 47 VCC (power), 48 TMS/IN1 (in), 49 NC, 50 GND (power), 51 I/O24 (io), 52 I/O25 (io), 53 I/O26 (io), 54 I/O27 (io), 55 I/O28 (io), 56 I/O29 (io), 57 I/O30 (io), 58 I/O31 (io), 59 I/O32 (io), 60 I/O33 (io), 61 I/O34 (io), 62 I/O35 (io), 63 GND (power), 64 I/O36 (io), 65 I/O37 (io), 66 VCC (power), 67 I/O38 (io), 68 I/O39 (io), 69 I/O40 (io), 70 I/O41 (io), 71 I/O42 (io), 72 I/O43 (io), 73 I/O44 (io), 74 I/O45 (io), 75 I/O46 (io), 76 I/O47 (io), 77 TCK/IN3 (in), 78 Y2 (in), 79 GND (power), 80 GOE0 (in), 81 VCC (power), 82 NC, 83 Y1 (in), 84 IN4 (in), 85 I/O48 (io), 86 I/O49 (io), 87 I/O50 (io), 88 I/O51 (io), 89 I/O52 (io), 90 I/O53 (io), 91 I/O54 (io), 92 I/O55 (io), 93 I/O56 (io), 94 I/O57 (io), 95 VCC (power), 96 I/O58 (io), 97 I/O59 (io), 98 GND (power), 99 I/O60 (io), 100 I/O61 (io), 101 I/O62 (io), 102 I/O63 (io), 103 I/O64 (io), 104 I/O65 (io), 105 I/O66 (io), 106 I/O67 (io), 107 I/O68 (io), 108 I/O69 (io), 109 I/O70 (io), 110 I/O71 (io), 111 GND (power), 112 TDO/IN2 (io), 113 IN5 (in), 114 VCC (power), 115 I/O72 (io), 116 I/O73 (io), 117 I/O74 (io), 118 I/O75 (io), 119 I/O76 (io), 120 I/O77 (io), 121 I/O78 (io), 122 I/O79 (io), 123 I/O80 (io), 124 I/O81 (io), 125 I/O82 (io), 126 I/O83 (io), 127 GND (power), 128 I/O84 (io)

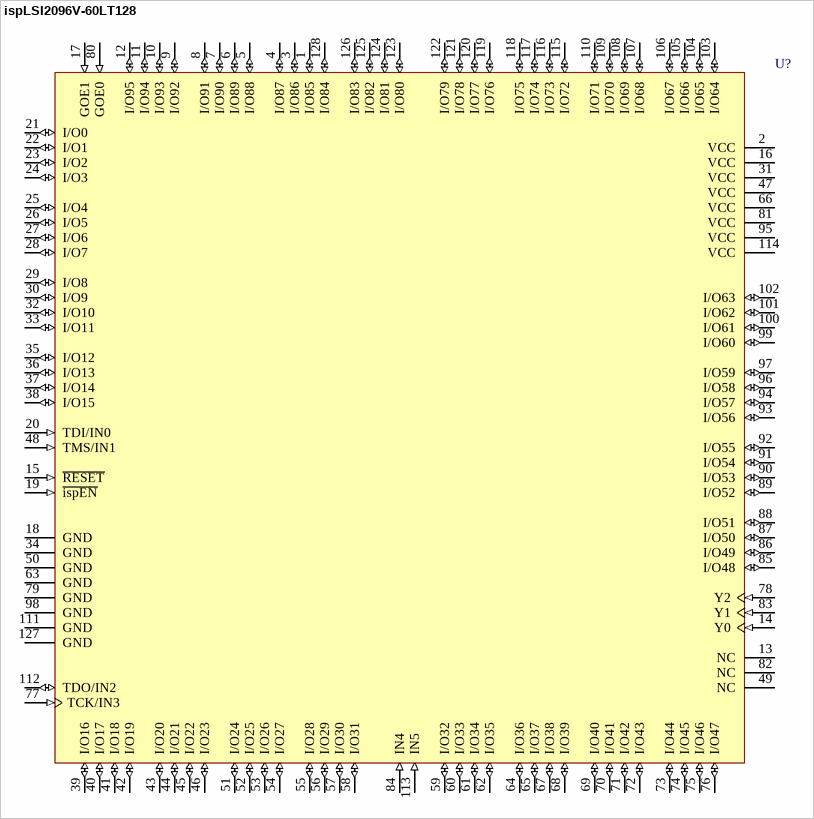
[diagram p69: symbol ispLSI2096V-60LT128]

## ispLSI2096V-60LT128
designator U?
3.3V High-Density Programmable Logic
footprint TQFP128_N (Thin QFP, 128-Leads, Body 14x14mm, Pitch 0.4mm, IPC Medium Density)
footprint TQFP128_L (Thin QFP, 128-Leads, Body 14x14mm, Pitch 0.4mm, IPC High Density)
footprint TQFP128_M (Thin QFP, 128-Leads, Body 14x14mm, Pitch 0.4mm, IPC Low Density)
3D model 2096V-TQFP128 (128-Pin Thin Quad Flat Pack 0.4 mm Pitch)
pins: 1 I/O85 (io), 2 VCC (power), 3 I/O86 (io), 4 I/O87 (io), 5 I/O88 (io), 6 I/O89 (io), 7 I/O90 (io), 8 I/O91 (io), 9 I/O92 (io), 10 I/O93 (io), 11 I/O94 (io), 12 I/O95 (io), 13 NC, 14 Y0 (in), 15 ~{RESET} (in), 16 VCC (power), 17 GOE1 (in), 18 GND (power), 19 ~{ispEN} (in), 20 TDI/IN0 (in), 21 I/O0 (io), 22 I/O1 (io), 23 I/O2 (io), 24 I/O3 (io), 25 I/O4 (io), 26 I/O5 (io), 27 I/O6 (io), 28 I/O7 (io), 29 I/O8 (io), 30 I/O9 (io), 31 VCC (power), 32 I/O10 (io), 33 I/O11 (io), 34 GND (power), 35 I/O12 (io), 36 I/O13 (io), 37 I/O14 (io), 38 I/O15 (io), 39 I/O16 (io), 40 I/O17 (io), 41 I/O18 (io), 42 I/O19 (io), 43 I/O20 (io), 44 I/O21 (io), 45 I/O22 (io), 46 I/O23 (io), 47 VCC (power), 48 TMS/IN1 (in), 49 NC, 50 GND (power), 51 I/O24 (io), 52 I/O25 (io), 53 I/O26 (io), 54 I/O27 (io), 55 I/O28 (io), 56 I/O29 (io), 57 I/O30 (io), 58 I/O31 (io), 59 I/O32 (io), 60 I/O33 (io), 61 I/O34 (io), 62 I/O35 (io), 63 GND (power), 64 I/O36 (io), 65 I/O37 (io), 66 VCC (power), 67 I/O38 (io), 68 I/O39 (io), 69 I/O40 (io), 70 I/O41 (io), 71 I/O42 (io), 72 I/O43 (io), 73 I/O44 (io), 74 I/O45 (io), 75 I/O46 (io), 76 I/O47 (io), 77 TCK/IN3 (in), 78 Y2 (in), 79 GND (power), 80 GOE0 (in), 81 VCC (power), 82 NC, 83 Y1 (in), 84 IN4 (in), 85 I/O48 (io), 86 I/O49 (io), 87 I/O50 (io), 88 I/O51 (io), 89 I/O52 (io), 90 I/O53 (io), 91 I/O54 (io), 92 I/O55 (io), 93 I/O56 (io), 94 I/O57 (io), 95 VCC (power), 96 I/O58 (io), 97 I/O59 (io), 98 GND (power), 99 I/O60 (io), 100 I/O61 (io), 101 I/O62 (io), 102 I/O63 (io), 103 I/O64 (io), 104 I/O65 (io), 105 I/O66 (io), 106 I/O67 (io), 107 I/O68 (io), 108 I/O69 (io), 109 I/O70 (io), 110 I/O71 (io), 111 GND (power), 112 TDO/IN2 (io), 113 IN5 (in), 114 VCC (power), 115 I/O72 (io), 116 I/O73 (io), 117 I/O74 (io), 118 I/O75 (io), 119 I/O76 (io), 120 I/O77 (io), 121 I/O78 (io), 122 I/O79 (io), 123 I/O80 (io), 124 I/O81 (io), 125 I/O82 (io), 126 I/O83 (io), 127 GND (power), 128 I/O84 (io)

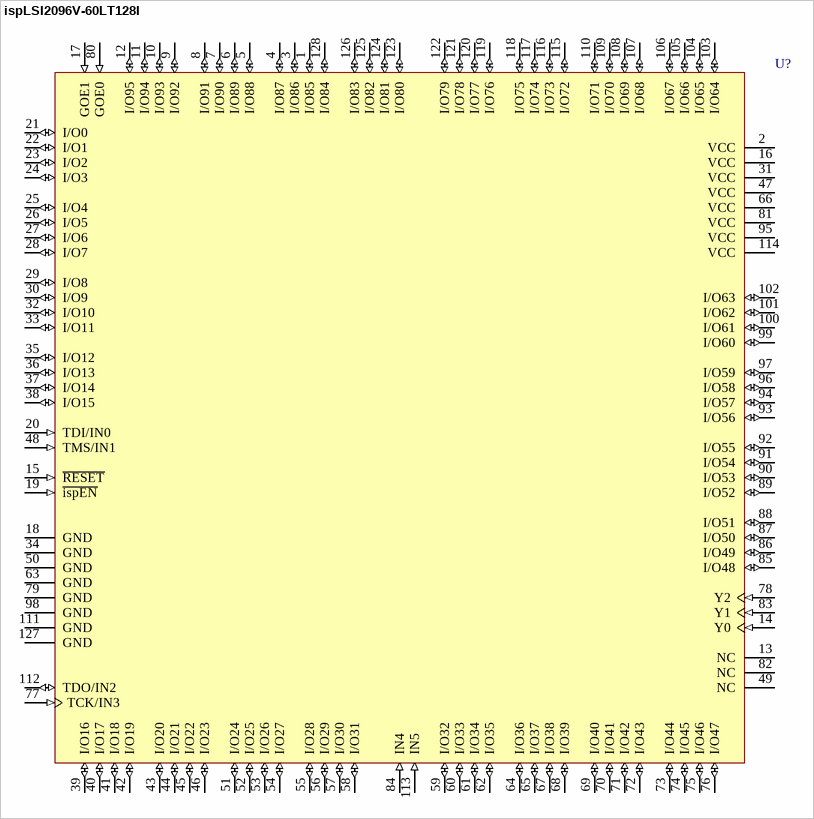
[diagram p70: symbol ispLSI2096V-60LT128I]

## ispLSI2096V-60LT128I
designator U?
3.3V High-Density Programmable Logic
footprint TQFP128_N (Thin QFP, 128-Leads, Body 14x14mm, Pitch 0.4mm, IPC Medium Density)
footprint TQFP128_L (Thin QFP, 128-Leads, Body 14x14mm, Pitch 0.4mm, IPC High Density)
footprint TQFP128_M (Thin QFP, 128-Leads, Body 14x14mm, Pitch 0.4mm, IPC Low Density)
3D model 2096V-TQFP128 (128-Pin Thin Quad Flat Pack 0.4 mm Pitch)
pins: 1 I/O85 (io), 2 VCC (power), 3 I/O86 (io), 4 I/O87 (io), 5 I/O88 (io), 6 I/O89 (io), 7 I/O90 (io), 8 I/O91 (io), 9 I/O92 (io), 10 I/O93 (io), 11 I/O94 (io), 12 I/O95 (io), 13 NC, 14 Y0 (in), 15 ~{RESET} (in), 16 VCC (power), 17 GOE1 (in), 18 GND (power), 19 ~{ispEN} (in), 20 TDI/IN0 (in), 21 I/O0 (io), 22 I/O1 (io), 23 I/O2 (io), 24 I/O3 (io), 25 I/O4 (io), 26 I/O5 (io), 27 I/O6 (io), 28 I/O7 (io), 29 I/O8 (io), 30 I/O9 (io), 31 VCC (power), 32 I/O10 (io), 33 I/O11 (io), 34 GND (power), 35 I/O12 (io), 36 I/O13 (io), 37 I/O14 (io), 38 I/O15 (io), 39 I/O16 (io), 40 I/O17 (io), 41 I/O18 (io), 42 I/O19 (io), 43 I/O20 (io), 44 I/O21 (io), 45 I/O22 (io), 46 I/O23 (io), 47 VCC (power), 48 TMS/IN1 (in), 49 NC, 50 GND (power), 51 I/O24 (io), 52 I/O25 (io), 53 I/O26 (io), 54 I/O27 (io), 55 I/O28 (io), 56 I/O29 (io), 57 I/O30 (io), 58 I/O31 (io), 59 I/O32 (io), 60 I/O33 (io), 61 I/O34 (io), 62 I/O35 (io), 63 GND (power), 64 I/O36 (io), 65 I/O37 (io), 66 VCC (power), 67 I/O38 (io), 68 I/O39 (io), 69 I/O40 (io), 70 I/O41 (io), 71 I/O42 (io), 72 I/O43 (io), 73 I/O44 (io), 74 I/O45 (io), 75 I/O46 (io), 76 I/O47 (io), 77 TCK/IN3 (in), 78 Y2 (in), 79 GND (power), 80 GOE0 (in), 81 VCC (power), 82 NC, 83 Y1 (in), 84 IN4 (in), 85 I/O48 (io), 86 I/O49 (io), 87 I/O50 (io), 88 I/O51 (io), 89 I/O52 (io), 90 I/O53 (io), 91 I/O54 (io), 92 I/O55 (io), 93 I/O56 (io), 94 I/O57 (io), 95 VCC (power), 96 I/O58 (io), 97 I/O59 (io), 98 GND (power), 99 I/O60 (io), 100 I/O61 (io), 101 I/O62 (io), 102 I/O63 (io), 103 I/O64 (io), 104 I/O65 (io), 105 I/O66 (io), 106 I/O67 (io), 107 I/O68 (io), 108 I/O69 (io), 109 I/O70 (io), 110 I/O71 (io), 111 GND (power), 112 TDO/IN2 (io), 113 IN5 (in), 114 VCC (power), 115 I/O72 (io), 116 I/O73 (io), 117 I/O74 (io), 118 I/O75 (io), 119 I/O76 (io), 120 I/O77 (io), 121 I/O78 (io), 122 I/O79 (io), 123 I/O80 (io), 124 I/O81 (io), 125 I/O82 (io), 126 I/O83 (io), 127 GND (power), 128 I/O84 (io)

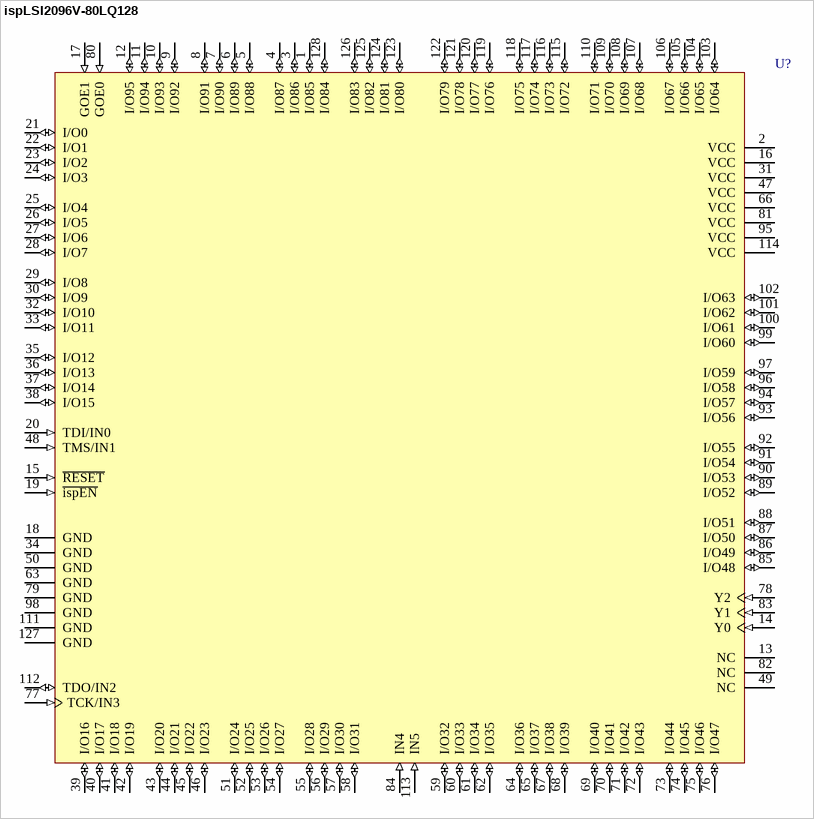
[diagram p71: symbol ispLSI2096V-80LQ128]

## ispLSI2096V-80LQ128
designator U?
3.3V High-Density Programmable Logic
footprint PQFP128_N (QFP, 128-Leads, Body 28x28mm, Pitch 0.8mm, IPC Medium Density)
footprint PQFP128_L (QFP, 128-Leads, Body 28x28mm, Pitch 0.8mm, IPC High Density)
footprint PQFP128_M (QFP, 128-Leads, Body 28x28mm, Pitch 0.8mm, IPC Low Density)
3D model 2096V-PQFP128 (128-Pin Quad Flat Pack 0.8 mm Pitch)
pins: 1 I/O85 (io), 2 VCC (power), 3 I/O86 (io), 4 I/O87 (io), 5 I/O88 (io), 6 I/O89 (io), 7 I/O90 (io), 8 I/O91 (io), 9 I/O92 (io), 10 I/O93 (io), 11 I/O94 (io), 12 I/O95 (io), 13 NC, 14 Y0 (in), 15 ~{RESET} (in), 16 VCC (power), 17 GOE1 (in), 18 GND (power), 19 ~{ispEN} (in), 20 TDI/IN0 (in), 21 I/O0 (io), 22 I/O1 (io), 23 I/O2 (io), 24 I/O3 (io), 25 I/O4 (io), 26 I/O5 (io), 27 I/O6 (io), 28 I/O7 (io), 29 I/O8 (io), 30 I/O9 (io), 31 VCC (power), 32 I/O10 (io), 33 I/O11 (io), 34 GND (power), 35 I/O12 (io), 36 I/O13 (io), 37 I/O14 (io), 38 I/O15 (io), 39 I/O16 (io), 40 I/O17 (io), 41 I/O18 (io), 42 I/O19 (io), 43 I/O20 (io), 44 I/O21 (io), 45 I/O22 (io), 46 I/O23 (io), 47 VCC (power), 48 TMS/IN1 (in), 49 NC, 50 GND (power), 51 I/O24 (io), 52 I/O25 (io), 53 I/O26 (io), 54 I/O27 (io), 55 I/O28 (io), 56 I/O29 (io), 57 I/O30 (io), 58 I/O31 (io), 59 I/O32 (io), 60 I/O33 (io), 61 I/O34 (io), 62 I/O35 (io), 63 GND (power), 64 I/O36 (io), 65 I/O37 (io), 66 VCC (power), 67 I/O38 (io), 68 I/O39 (io), 69 I/O40 (io), 70 I/O41 (io), 71 I/O42 (io), 72 I/O43 (io), 73 I/O44 (io), 74 I/O45 (io), 75 I/O46 (io), 76 I/O47 (io), 77 TCK/IN3 (in), 78 Y2 (in), 79 GND (power), 80 GOE0 (in), 81 VCC (power), 82 NC, 83 Y1 (in), 84 IN4 (in), 85 I/O48 (io), 86 I/O49 (io), 87 I/O50 (io), 88 I/O51 (io), 89 I/O52 (io), 90 I/O53 (io), 91 I/O54 (io), 92 I/O55 (io), 93 I/O56 (io), 94 I/O57 (io), 95 VCC (power), 96 I/O58 (io), 97 I/O59 (io), 98 GND (power), 99 I/O60 (io), 100 I/O61 (io), 101 I/O62 (io), 102 I/O63 (io), 103 I/O64 (io), 104 I/O65 (io), 105 I/O66 (io), 106 I/O67 (io), 107 I/O68 (io), 108 I/O69 (io), 109 I/O70 (io), 110 I/O71 (io), 111 GND (power), 112 TDO/IN2 (io), 113 IN5 (in), 114 VCC (power), 115 I/O72 (io), 116 I/O73 (io), 117 I/O74 (io), 118 I/O75 (io), 119 I/O76 (io), 120 I/O77 (io), 121 I/O78 (io), 122 I/O79 (io), 123 I/O80 (io), 124 I/O81 (io), 125 I/O82 (io), 126 I/O83 (io), 127 GND (power), 128 I/O84 (io)

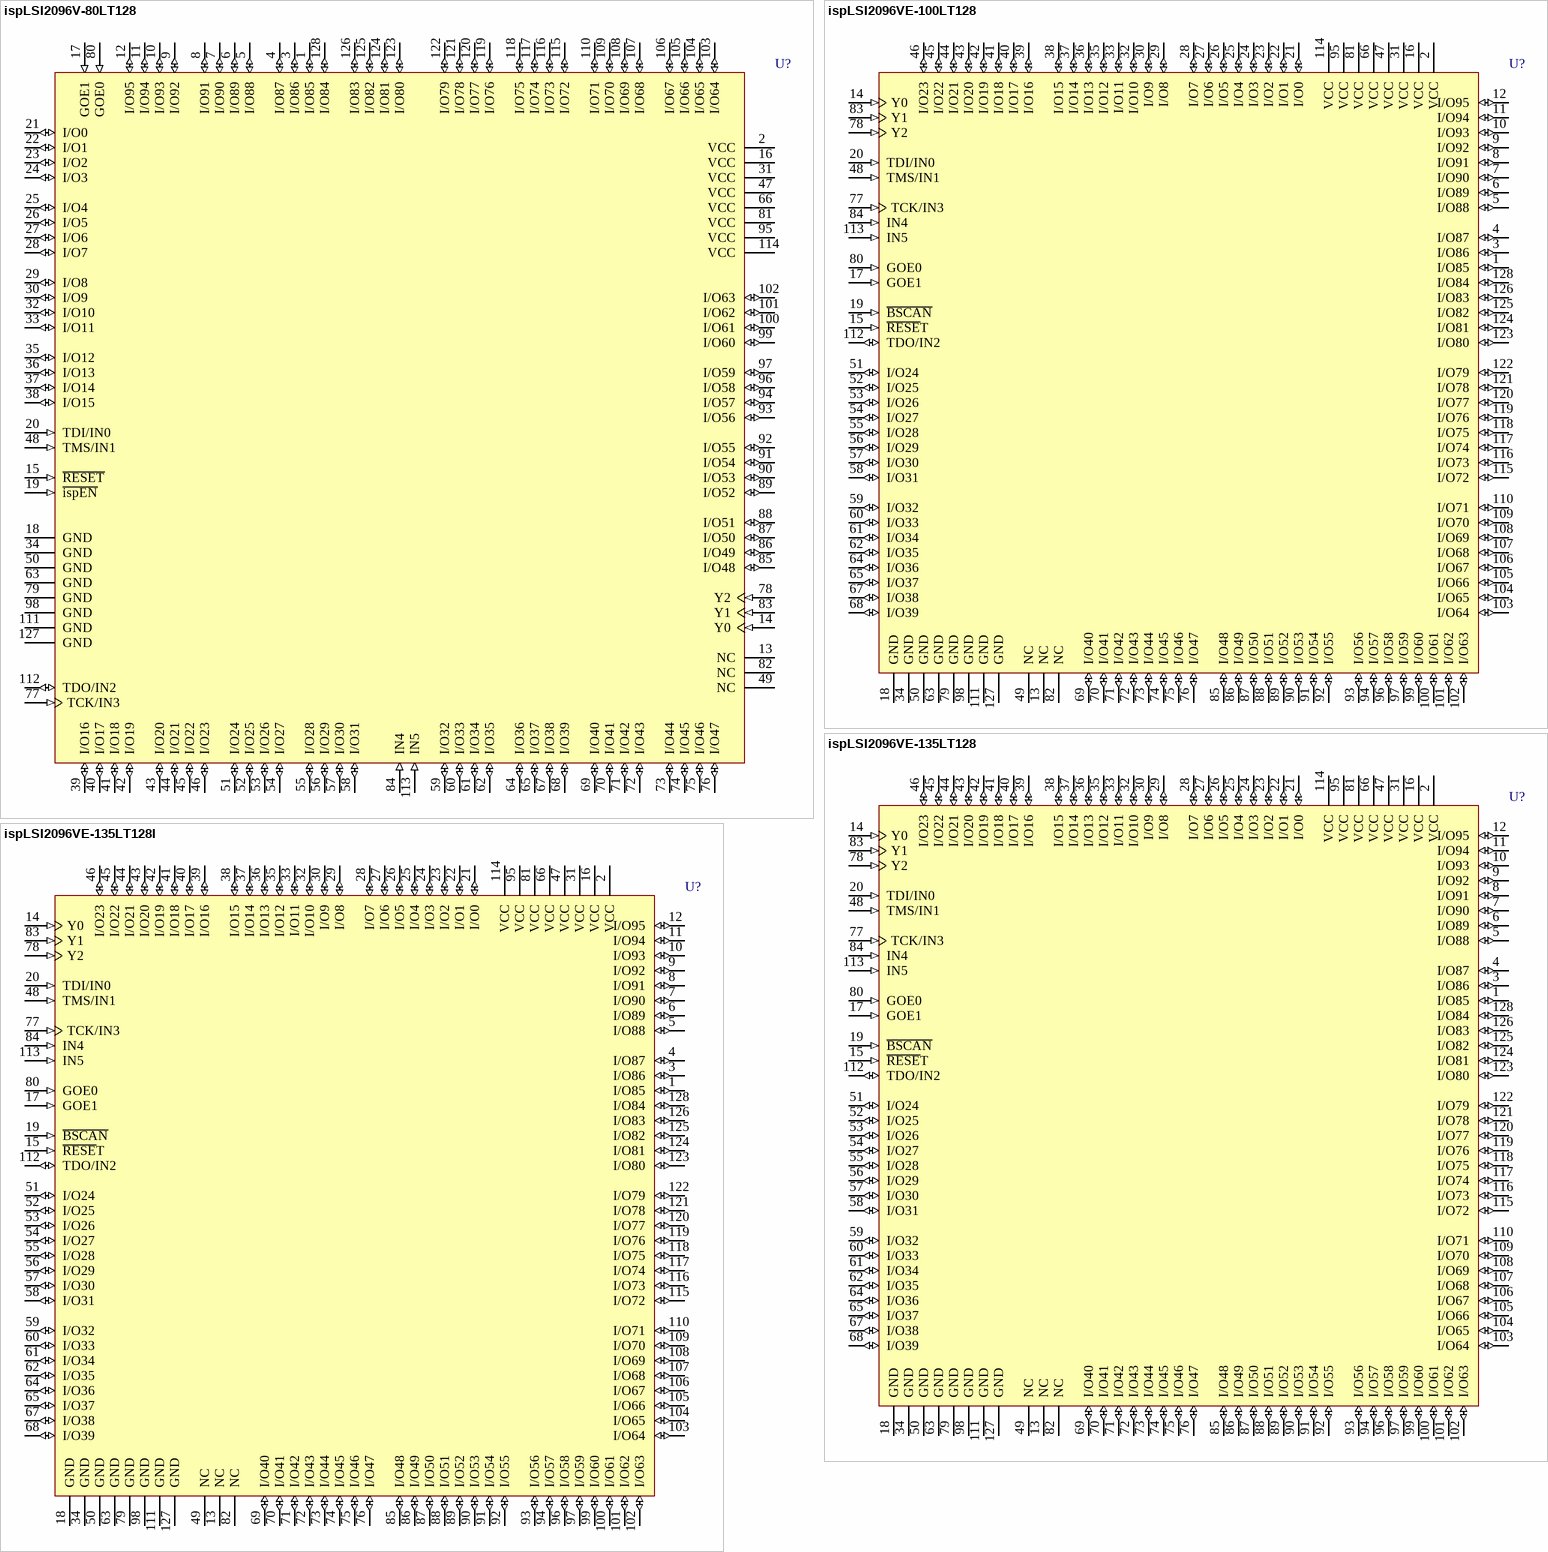
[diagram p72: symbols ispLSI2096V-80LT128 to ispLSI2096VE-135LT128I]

## ispLSI2096V-80LT128
designator U?
3.3V High-Density Programmable Logic
footprint TQFP128_N (Thin QFP, 128-Leads, Body 14x14mm, Pitch 0.4mm, IPC Medium Density)
footprint TQFP128_L (Thin QFP, 128-Leads, Body 14x14mm, Pitch 0.4mm, IPC High Density)
footprint TQFP128_M (Thin QFP, 128-Leads, Body 14x14mm, Pitch 0.4mm, IPC Low Density)
3D model 2096V-TQFP128 (128-Pin Thin Quad Flat Pack 0.4 mm Pitch)
pins: 1 I/O85 (io), 2 VCC (power), 3 I/O86 (io), 4 I/O87 (io), 5 I/O88 (io), 6 I/O89 (io), 7 I/O90 (io), 8 I/O91 (io), 9 I/O92 (io), 10 I/O93 (io), 11 I/O94 (io), 12 I/O95 (io), 13 NC, 14 Y0 (in), 15 ~{RESET} (in), 16 VCC (power), 17 GOE1 (in), 18 GND (power), 19 ~{ispEN} (in), 20 TDI/IN0 (in), 21 I/O0 (io), 22 I/O1 (io), 23 I/O2 (io), 24 I/O3 (io), 25 I/O4 (io), 26 I/O5 (io), 27 I/O6 (io), 28 I/O7 (io), 29 I/O8 (io), 30 I/O9 (io), 31 VCC (power), 32 I/O10 (io), 33 I/O11 (io), 34 GND (power), 35 I/O12 (io), 36 I/O13 (io), 37 I/O14 (io), 38 I/O15 (io), 39 I/O16 (io), 40 I/O17 (io), 41 I/O18 (io), 42 I/O19 (io), 43 I/O20 (io), 44 I/O21 (io), 45 I/O22 (io), 46 I/O23 (io), 47 VCC (power), 48 TMS/IN1 (in), 49 NC, 50 GND (power), 51 I/O24 (io), 52 I/O25 (io), 53 I/O26 (io), 54 I/O27 (io), 55 I/O28 (io), 56 I/O29 (io), 57 I/O30 (io), 58 I/O31 (io), 59 I/O32 (io), 60 I/O33 (io), 61 I/O34 (io), 62 I/O35 (io), 63 GND (power), 64 I/O36 (io), 65 I/O37 (io), 66 VCC (power), 67 I/O38 (io), 68 I/O39 (io), 69 I/O40 (io), 70 I/O41 (io), 71 I/O42 (io), 72 I/O43 (io), 73 I/O44 (io), 74 I/O45 (io), 75 I/O46 (io), 76 I/O47 (io), 77 TCK/IN3 (in), 78 Y2 (in), 79 GND (power), 80 GOE0 (in), 81 VCC (power), 82 NC, 83 Y1 (in), 84 IN4 (in), 85 I/O48 (io), 86 I/O49 (io), 87 I/O50 (io), 88 I/O51 (io), 89 I/O52 (io), 90 I/O53 (io), 91 I/O54 (io), 92 I/O55 (io), 93 I/O56 (io), 94 I/O57 (io), 95 VCC (power), 96 I/O58 (io), 97 I/O59 (io), 98 GND (power), 99 I/O60 (io), 100 I/O61 (io), 101 I/O62 (io), 102 I/O63 (io), 103 I/O64 (io), 104 I/O65 (io), 105 I/O66 (io), 106 I/O67 (io), 107 I/O68 (io), 108 I/O69 (io), 109 I/O70 (io), 110 I/O71 (io), 111 GND (power), 112 TDO/IN2 (io), 113 IN5 (in), 114 VCC (power), 115 I/O72 (io), 116 I/O73 (io), 117 I/O74 (io), 118 I/O75 (io), 119 I/O76 (io), 120 I/O77 (io), 121 I/O78 (io), 122 I/O79 (io), 123 I/O80 (io), 124 I/O81 (io), 125 I/O82 (io), 126 I/O83 (io), 127 GND (power), 128 I/O84 (io)

## ispLSI2096VE-100LT128
designator U?
3.3V In-System Programmable SuperFAST High Density PLD
footprint TQFP128_N (Thin QFP, 128-Leads, Body 14x14mm, Pitch 0.4mm, IPC Medium Density)
footprint TQFP128_L (Thin QFP, 128-Leads, Body 14x14mm, Pitch 0.4mm, IPC High Density)
footprint TQFP128_M (Thin QFP, 128-Leads, Body 14x14mm, Pitch 0.4mm, IPC Low Density)
3D model 2096VE-TQFP128 (128-Pin Thin Quad Flat Pack 0.4 mm Pitch)
pins: 1 I/O85 (io), 2 VCC (power), 3 I/O86 (io), 4 I/O87 (io), 5 I/O88 (io), 6 I/O89 (io), 7 I/O90 (io), 8 I/O91 (io), 9 I/O92 (io), 10 I/O93 (io), 11 I/O94 (io), 12 I/O95 (io), 13 NC, 14 Y0 (in), 15 ~{RESE}T (in), 16 VCC (power), 17 GOE1 (in), 18 GND (power), 19 ~{BSCAN} (in), 20 TDI/IN0 (in), 21 I/O0 (io), 22 I/O1 (io), 23 I/O2 (io), 24 I/O3 (io), 25 I/O4 (io), 26 I/O5 (io), 27 I/O6 (io), 28 I/O7 (io), 29 I/O8 (io), 30 I/O9 (io), 31 VCC (power), 32 I/O10 (io), 33 I/O11 (io), 34 GND (power), 35 I/O12 (io), 36 I/O13 (io), 37 I/O14 (io), 38 I/O15 (io), 39 I/O16 (io), 40 I/O17 (io), 41 I/O18 (io), 42 I/O19 (io), 43 I/O20 (io), 44 I/O21 (io), 45 I/O22 (io), 46 I/O23 (io), 47 VCC (power), 48 TMS/IN1 (in), 49 NC, 50 GND (power), 51 I/O24 (io), 52 I/O25 (io), 53 I/O26 (io), 54 I/O27 (io), 55 I/O28 (io), 56 I/O29 (io), 57 I/O30 (io), 58 I/O31 (io), 59 I/O32 (io), 60 I/O33 (io), 61 I/O34 (io), 62 I/O35 (io), 63 GND (power), 64 I/O36 (io), 65 I/O37 (io), 66 VCC (power), 67 I/O38 (io), 68 I/O39 (io), 69 I/O40 (io), 70 I/O41 (io), 71 I/O42 (io), 72 I/O43 (io), 73 I/O44 (io), 74 I/O45 (io), 75 I/O46 (io), 76 I/O47 (io), 77 TCK/IN3 (in), 78 Y2 (in), 79 GND (power), 80 GOE0 (in), 81 VCC (power), 82 NC, 83 Y1 (in), 84 IN4 (in), 85 I/O48 (io), 86 I/O49 (io), 87 I/O50 (io), 88 I/O51 (io), 89 I/O52 (io), 90 I/O53 (io), 91 I/O54 (io), 92 I/O55 (io), 93 I/O56 (io), 94 I/O57 (io), 95 VCC (power), 96 I/O58 (io), 97 I/O59 (io), 98 GND (power), 99 I/O60 (io), 100 I/O61 (io), 101 I/O62 (io), 102 I/O63 (io), 103 I/O64 (io), 104 I/O65 (io), 105 I/O66 (io), 106 I/O67 (io), 107 I/O68 (io), 108 I/O69 (io), 109 I/O70 (io), 110 I/O71 (io), 111 GND (power), 112 TDO/IN2 (io), 113 IN5 (in), 114 VCC (power), 115 I/O72 (io), 116 I/O73 (io), 117 I/O74 (io), 118 I/O75 (io), 119 I/O76 (io), 120 I/O77 (io), 121 I/O78 (io), 122 I/O79 (io), 123 I/O80 (io), 124 I/O81 (io), 125 I/O82 (io), 126 I/O83 (io), 127 GND (power), 128 I/O84 (io)

## ispLSI2096VE-135LT128
designator U?
3.3V In-System Programmable SuperFAST High Density PLD
footprint TQFP128_N (Thin QFP, 128-Leads, Body 14x14mm, Pitch 0.4mm, IPC Medium Density)
footprint TQFP128_L (Thin QFP, 128-Leads, Body 14x14mm, Pitch 0.4mm, IPC High Density)
footprint TQFP128_M (Thin QFP, 128-Leads, Body 14x14mm, Pitch 0.4mm, IPC Low Density)
3D model 2096VE-TQFP128 (128-Pin Thin Quad Flat Pack 0.4 mm Pitch)
pins: 1 I/O85 (io), 2 VCC (power), 3 I/O86 (io), 4 I/O87 (io), 5 I/O88 (io), 6 I/O89 (io), 7 I/O90 (io), 8 I/O91 (io), 9 I/O92 (io), 10 I/O93 (io), 11 I/O94 (io), 12 I/O95 (io), 13 NC, 14 Y0 (in), 15 ~{RESE}T (in), 16 VCC (power), 17 GOE1 (in), 18 GND (power), 19 ~{BSCAN} (in), 20 TDI/IN0 (in), 21 I/O0 (io), 22 I/O1 (io), 23 I/O2 (io), 24 I/O3 (io), 25 I/O4 (io), 26 I/O5 (io), 27 I/O6 (io), 28 I/O7 (io), 29 I/O8 (io), 30 I/O9 (io), 31 VCC (power), 32 I/O10 (io), 33 I/O11 (io), 34 GND (power), 35 I/O12 (io), 36 I/O13 (io), 37 I/O14 (io), 38 I/O15 (io), 39 I/O16 (io), 40 I/O17 (io), 41 I/O18 (io), 42 I/O19 (io), 43 I/O20 (io), 44 I/O21 (io), 45 I/O22 (io), 46 I/O23 (io), 47 VCC (power), 48 TMS/IN1 (in), 49 NC, 50 GND (power), 51 I/O24 (io), 52 I/O25 (io), 53 I/O26 (io), 54 I/O27 (io), 55 I/O28 (io), 56 I/O29 (io), 57 I/O30 (io), 58 I/O31 (io), 59 I/O32 (io), 60 I/O33 (io), 61 I/O34 (io), 62 I/O35 (io), 63 GND (power), 64 I/O36 (io), 65 I/O37 (io), 66 VCC (power), 67 I/O38 (io), 68 I/O39 (io), 69 I/O40 (io), 70 I/O41 (io), 71 I/O42 (io), 72 I/O43 (io), 73 I/O44 (io), 74 I/O45 (io), 75 I/O46 (io), 76 I/O47 (io), 77 TCK/IN3 (in), 78 Y2 (in), 79 GND (power), 80 GOE0 (in), 81 VCC (power), 82 NC, 83 Y1 (in), 84 IN4 (in), 85 I/O48 (io), 86 I/O49 (io), 87 I/O50 (io), 88 I/O51 (io), 89 I/O52 (io), 90 I/O53 (io), 91 I/O54 (io), 92 I/O55 (io), 93 I/O56 (io), 94 I/O57 (io), 95 VCC (power), 96 I/O58 (io), 97 I/O59 (io), 98 GND (power), 99 I/O60 (io), 100 I/O61 (io), 101 I/O62 (io), 102 I/O63 (io), 103 I/O64 (io), 104 I/O65 (io), 105 I/O66 (io), 106 I/O67 (io), 107 I/O68 (io), 108 I/O69 (io), 109 I/O70 (io), 110 I/O71 (io), 111 GND (power), 112 TDO/IN2 (io), 113 IN5 (in), 114 VCC (power), 115 I/O72 (io), 116 I/O73 (io), 117 I/O74 (io), 118 I/O75 (io), 119 I/O76 (io), 120 I/O77 (io), 121 I/O78 (io), 122 I/O79 (io), 123 I/O80 (io), 124 I/O81 (io), 125 I/O82 (io), 126 I/O83 (io), 127 GND (power), 128 I/O84 (io)

## ispLSI2096VE-135LT128I
designator U?
3.3V In-System Programmable SuperFAST High Density PLD
footprint TQFP128_N (Thin QFP, 128-Leads, Body 14x14mm, Pitch 0.4mm, IPC Medium Density)
footprint TQFP128_L (Thin QFP, 128-Leads, Body 14x14mm, Pitch 0.4mm, IPC High Density)
footprint TQFP128_M (Thin QFP, 128-Leads, Body 14x14mm, Pitch 0.4mm, IPC Low Density)
3D model 2096VE-TQFP128 (128-Pin Thin Quad Flat Pack 0.4 mm Pitch)
pins: 1 I/O85 (io), 2 VCC (power), 3 I/O86 (io), 4 I/O87 (io), 5 I/O88 (io), 6 I/O89 (io), 7 I/O90 (io), 8 I/O91 (io), 9 I/O92 (io), 10 I/O93 (io), 11 I/O94 (io), 12 I/O95 (io), 13 NC, 14 Y0 (in), 15 ~{RESE}T (in), 16 VCC (power), 17 GOE1 (in), 18 GND (power), 19 ~{BSCAN} (in), 20 TDI/IN0 (in), 21 I/O0 (io), 22 I/O1 (io), 23 I/O2 (io), 24 I/O3 (io), 25 I/O4 (io), 26 I/O5 (io), 27 I/O6 (io), 28 I/O7 (io), 29 I/O8 (io), 30 I/O9 (io), 31 VCC (power), 32 I/O10 (io), 33 I/O11 (io), 34 GND (power), 35 I/O12 (io), 36 I/O13 (io), 37 I/O14 (io), 38 I/O15 (io), 39 I/O16 (io), 40 I/O17 (io), 41 I/O18 (io), 42 I/O19 (io), 43 I/O20 (io), 44 I/O21 (io), 45 I/O22 (io), 46 I/O23 (io), 47 VCC (power), 48 TMS/IN1 (in), 49 NC, 50 GND (power), 51 I/O24 (io), 52 I/O25 (io), 53 I/O26 (io), 54 I/O27 (io), 55 I/O28 (io), 56 I/O29 (io), 57 I/O30 (io), 58 I/O31 (io), 59 I/O32 (io), 60 I/O33 (io), 61 I/O34 (io), 62 I/O35 (io), 63 GND (power), 64 I/O36 (io), 65 I/O37 (io), 66 VCC (power), 67 I/O38 (io), 68 I/O39 (io), 69 I/O40 (io), 70 I/O41 (io), 71 I/O42 (io), 72 I/O43 (io), 73 I/O44 (io), 74 I/O45 (io), 75 I/O46 (io), 76 I/O47 (io), 77 TCK/IN3 (in), 78 Y2 (in), 79 GND (power), 80 GOE0 (in), 81 VCC (power), 82 NC, 83 Y1 (in), 84 IN4 (in), 85 I/O48 (io), 86 I/O49 (io), 87 I/O50 (io), 88 I/O51 (io), 89 I/O52 (io), 90 I/O53 (io), 91 I/O54 (io), 92 I/O55 (io), 93 I/O56 (io), 94 I/O57 (io), 95 VCC (power), 96 I/O58 (io), 97 I/O59 (io), 98 GND (power), 99 I/O60 (io), 100 I/O61 (io), 101 I/O62 (io), 102 I/O63 (io), 103 I/O64 (io), 104 I/O65 (io), 105 I/O66 (io), 106 I/O67 (io), 107 I/O68 (io), 108 I/O69 (io), 109 I/O70 (io), 110 I/O71 (io), 111 GND (power), 112 TDO/IN2 (io), 113 IN5 (in), 114 VCC (power), 115 I/O72 (io), 116 I/O73 (io), 117 I/O74 (io), 118 I/O75 (io), 119 I/O76 (io), 120 I/O77 (io), 121 I/O78 (io), 122 I/O79 (io), 123 I/O80 (io), 124 I/O81 (io), 125 I/O82 (io), 126 I/O83 (io), 127 GND (power), 128 I/O84 (io)

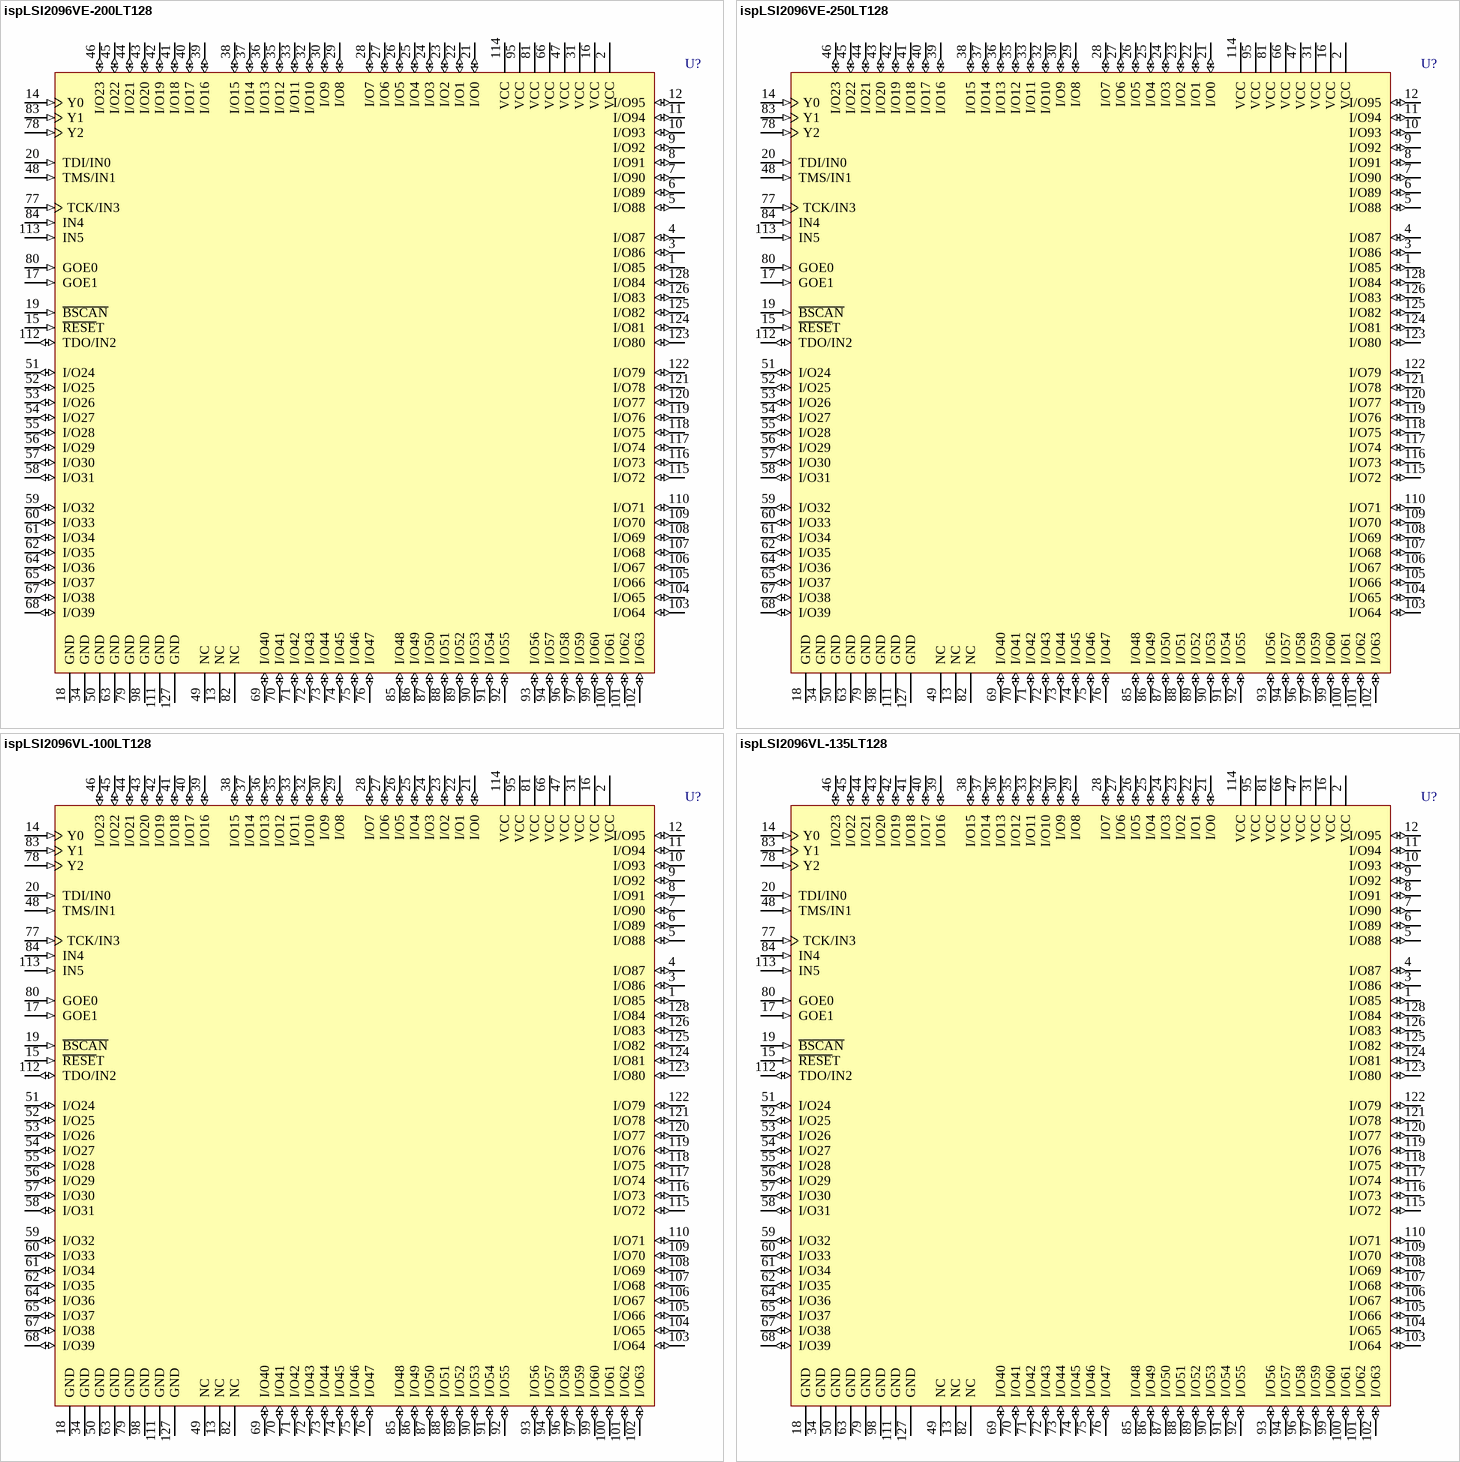
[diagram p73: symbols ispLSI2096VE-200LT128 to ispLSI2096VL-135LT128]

## ispLSI2096VE-200LT128
designator U?
3.3V In-System Programmable SuperFAST High Density PLD
footprint TQFP128_N (Thin QFP, 128-Leads, Body 14x14mm, Pitch 0.4mm, IPC Medium Density)
footprint TQFP128_L (Thin QFP, 128-Leads, Body 14x14mm, Pitch 0.4mm, IPC High Density)
footprint TQFP128_M (Thin QFP, 128-Leads, Body 14x14mm, Pitch 0.4mm, IPC Low Density)
3D model 2096VE-TQFP128 (128-Pin Thin Quad Flat Pack 0.4 mm Pitch)
pins: 1 I/O85 (io), 2 VCC (power), 3 I/O86 (io), 4 I/O87 (io), 5 I/O88 (io), 6 I/O89 (io), 7 I/O90 (io), 8 I/O91 (io), 9 I/O92 (io), 10 I/O93 (io), 11 I/O94 (io), 12 I/O95 (io), 13 NC, 14 Y0 (in), 15 ~{RESE}T (in), 16 VCC (power), 17 GOE1 (in), 18 GND (power), 19 ~{BSCAN} (in), 20 TDI/IN0 (in), 21 I/O0 (io), 22 I/O1 (io), 23 I/O2 (io), 24 I/O3 (io), 25 I/O4 (io), 26 I/O5 (io), 27 I/O6 (io), 28 I/O7 (io), 29 I/O8 (io), 30 I/O9 (io), 31 VCC (power), 32 I/O10 (io), 33 I/O11 (io), 34 GND (power), 35 I/O12 (io), 36 I/O13 (io), 37 I/O14 (io), 38 I/O15 (io), 39 I/O16 (io), 40 I/O17 (io), 41 I/O18 (io), 42 I/O19 (io), 43 I/O20 (io), 44 I/O21 (io), 45 I/O22 (io), 46 I/O23 (io), 47 VCC (power), 48 TMS/IN1 (in), 49 NC, 50 GND (power), 51 I/O24 (io), 52 I/O25 (io), 53 I/O26 (io), 54 I/O27 (io), 55 I/O28 (io), 56 I/O29 (io), 57 I/O30 (io), 58 I/O31 (io), 59 I/O32 (io), 60 I/O33 (io), 61 I/O34 (io), 62 I/O35 (io), 63 GND (power), 64 I/O36 (io), 65 I/O37 (io), 66 VCC (power), 67 I/O38 (io), 68 I/O39 (io), 69 I/O40 (io), 70 I/O41 (io), 71 I/O42 (io), 72 I/O43 (io), 73 I/O44 (io), 74 I/O45 (io), 75 I/O46 (io), 76 I/O47 (io), 77 TCK/IN3 (in), 78 Y2 (in), 79 GND (power), 80 GOE0 (in), 81 VCC (power), 82 NC, 83 Y1 (in), 84 IN4 (in), 85 I/O48 (io), 86 I/O49 (io), 87 I/O50 (io), 88 I/O51 (io), 89 I/O52 (io), 90 I/O53 (io), 91 I/O54 (io), 92 I/O55 (io), 93 I/O56 (io), 94 I/O57 (io), 95 VCC (power), 96 I/O58 (io), 97 I/O59 (io), 98 GND (power), 99 I/O60 (io), 100 I/O61 (io), 101 I/O62 (io), 102 I/O63 (io), 103 I/O64 (io), 104 I/O65 (io), 105 I/O66 (io), 106 I/O67 (io), 107 I/O68 (io), 108 I/O69 (io), 109 I/O70 (io), 110 I/O71 (io), 111 GND (power), 112 TDO/IN2 (io), 113 IN5 (in), 114 VCC (power), 115 I/O72 (io), 116 I/O73 (io), 117 I/O74 (io), 118 I/O75 (io), 119 I/O76 (io), 120 I/O77 (io), 121 I/O78 (io), 122 I/O79 (io), 123 I/O80 (io), 124 I/O81 (io), 125 I/O82 (io), 126 I/O83 (io), 127 GND (power), 128 I/O84 (io)

## ispLSI2096VE-250LT128
designator U?
3.3V In-System Programmable SuperFAST High Density PLD
footprint TQFP128_N (Thin QFP, 128-Leads, Body 14x14mm, Pitch 0.4mm, IPC Medium Density)
footprint TQFP128_L (Thin QFP, 128-Leads, Body 14x14mm, Pitch 0.4mm, IPC High Density)
footprint TQFP128_M (Thin QFP, 128-Leads, Body 14x14mm, Pitch 0.4mm, IPC Low Density)
3D model 2096VE-TQFP128 (128-Pin Thin Quad Flat Pack 0.4 mm Pitch)
pins: 1 I/O85 (io), 2 VCC (power), 3 I/O86 (io), 4 I/O87 (io), 5 I/O88 (io), 6 I/O89 (io), 7 I/O90 (io), 8 I/O91 (io), 9 I/O92 (io), 10 I/O93 (io), 11 I/O94 (io), 12 I/O95 (io), 13 NC, 14 Y0 (in), 15 ~{RESE}T (in), 16 VCC (power), 17 GOE1 (in), 18 GND (power), 19 ~{BSCAN} (in), 20 TDI/IN0 (in), 21 I/O0 (io), 22 I/O1 (io), 23 I/O2 (io), 24 I/O3 (io), 25 I/O4 (io), 26 I/O5 (io), 27 I/O6 (io), 28 I/O7 (io), 29 I/O8 (io), 30 I/O9 (io), 31 VCC (power), 32 I/O10 (io), 33 I/O11 (io), 34 GND (power), 35 I/O12 (io), 36 I/O13 (io), 37 I/O14 (io), 38 I/O15 (io), 39 I/O16 (io), 40 I/O17 (io), 41 I/O18 (io), 42 I/O19 (io), 43 I/O20 (io), 44 I/O21 (io), 45 I/O22 (io), 46 I/O23 (io), 47 VCC (power), 48 TMS/IN1 (in), 49 NC, 50 GND (power), 51 I/O24 (io), 52 I/O25 (io), 53 I/O26 (io), 54 I/O27 (io), 55 I/O28 (io), 56 I/O29 (io), 57 I/O30 (io), 58 I/O31 (io), 59 I/O32 (io), 60 I/O33 (io), 61 I/O34 (io), 62 I/O35 (io), 63 GND (power), 64 I/O36 (io), 65 I/O37 (io), 66 VCC (power), 67 I/O38 (io), 68 I/O39 (io), 69 I/O40 (io), 70 I/O41 (io), 71 I/O42 (io), 72 I/O43 (io), 73 I/O44 (io), 74 I/O45 (io), 75 I/O46 (io), 76 I/O47 (io), 77 TCK/IN3 (in), 78 Y2 (in), 79 GND (power), 80 GOE0 (in), 81 VCC (power), 82 NC, 83 Y1 (in), 84 IN4 (in), 85 I/O48 (io), 86 I/O49 (io), 87 I/O50 (io), 88 I/O51 (io), 89 I/O52 (io), 90 I/O53 (io), 91 I/O54 (io), 92 I/O55 (io), 93 I/O56 (io), 94 I/O57 (io), 95 VCC (power), 96 I/O58 (io), 97 I/O59 (io), 98 GND (power), 99 I/O60 (io), 100 I/O61 (io), 101 I/O62 (io), 102 I/O63 (io), 103 I/O64 (io), 104 I/O65 (io), 105 I/O66 (io), 106 I/O67 (io), 107 I/O68 (io), 108 I/O69 (io), 109 I/O70 (io), 110 I/O71 (io), 111 GND (power), 112 TDO/IN2 (io), 113 IN5 (in), 114 VCC (power), 115 I/O72 (io), 116 I/O73 (io), 117 I/O74 (io), 118 I/O75 (io), 119 I/O76 (io), 120 I/O77 (io), 121 I/O78 (io), 122 I/O79 (io), 123 I/O80 (io), 124 I/O81 (io), 125 I/O82 (io), 126 I/O83 (io), 127 GND (power), 128 I/O84 (io)

## ispLSI2096VL-100LT128
designator U?
2.5V In-System Programmable SuperFAST High Density PLD
footprint TQFP128_N (Thin QFP, 128-Leads, Body 14x14mm, Pitch 0.4mm, IPC Medium Density)
footprint TQFP128_L (Thin QFP, 128-Leads, Body 14x14mm, Pitch 0.4mm, IPC High Density)
footprint TQFP128_M (Thin QFP, 128-Leads, Body 14x14mm, Pitch 0.4mm, IPC Low Density)
3D model 2096VL-TQFP128 (128-Pin Thin Quad Flat Pack 0.4 mm Pitch)
pins: 1 I/O85 (io), 2 VCC (power), 3 I/O86 (io), 4 I/O87 (io), 5 I/O88 (io), 6 I/O89 (io), 7 I/O90 (io), 8 I/O91 (io), 9 I/O92 (io), 10 I/O93 (io), 11 I/O94 (io), 12 I/O95 (io), 13 NC, 14 Y0 (in), 15 ~{RESE}T (in), 16 VCC (power), 17 GOE1 (in), 18 GND (power), 19 ~{BSCAN} (in), 20 TDI/IN0 (in), 21 I/O0 (io), 22 I/O1 (io), 23 I/O2 (io), 24 I/O3 (io), 25 I/O4 (io), 26 I/O5 (io), 27 I/O6 (io), 28 I/O7 (io), 29 I/O8 (io), 30 I/O9 (io), 31 VCC (power), 32 I/O10 (io), 33 I/O11 (io), 34 GND (power), 35 I/O12 (io), 36 I/O13 (io), 37 I/O14 (io), 38 I/O15 (io), 39 I/O16 (io), 40 I/O17 (io), 41 I/O18 (io), 42 I/O19 (io), 43 I/O20 (io), 44 I/O21 (io), 45 I/O22 (io), 46 I/O23 (io), 47 VCC (power), 48 TMS/IN1 (in), 49 NC, 50 GND (power), 51 I/O24 (io), 52 I/O25 (io), 53 I/O26 (io), 54 I/O27 (io), 55 I/O28 (io), 56 I/O29 (io), 57 I/O30 (io), 58 I/O31 (io), 59 I/O32 (io), 60 I/O33 (io), 61 I/O34 (io), 62 I/O35 (io), 63 GND (power), 64 I/O36 (io), 65 I/O37 (io), 66 VCC (power), 67 I/O38 (io), 68 I/O39 (io), 69 I/O40 (io), 70 I/O41 (io), 71 I/O42 (io), 72 I/O43 (io), 73 I/O44 (io), 74 I/O45 (io), 75 I/O46 (io), 76 I/O47 (io), 77 TCK/IN3 (in), 78 Y2 (in), 79 GND (power), 80 GOE0 (in), 81 VCC (power), 82 NC, 83 Y1 (in), 84 IN4 (in), 85 I/O48 (io), 86 I/O49 (io), 87 I/O50 (io), 88 I/O51 (io), 89 I/O52 (io), 90 I/O53 (io), 91 I/O54 (io), 92 I/O55 (io), 93 I/O56 (io), 94 I/O57 (io), 95 VCC (power), 96 I/O58 (io), 97 I/O59 (io), 98 GND (power), 99 I/O60 (io), 100 I/O61 (io), 101 I/O62 (io), 102 I/O63 (io), 103 I/O64 (io), 104 I/O65 (io), 105 I/O66 (io), 106 I/O67 (io), 107 I/O68 (io), 108 I/O69 (io), 109 I/O70 (io), 110 I/O71 (io), 111 GND (power), 112 TDO/IN2 (io), 113 IN5 (in), 114 VCC (power), 115 I/O72 (io), 116 I/O73 (io), 117 I/O74 (io), 118 I/O75 (io), 119 I/O76 (io), 120 I/O77 (io), 121 I/O78 (io), 122 I/O79 (io), 123 I/O80 (io), 124 I/O81 (io), 125 I/O82 (io), 126 I/O83 (io), 127 GND (power), 128 I/O84 (io)

## ispLSI2096VL-135LT128
designator U?
2.5V In-System Programmable SuperFAST High Density PLD
footprint TQFP128_N (Thin QFP, 128-Leads, Body 14x14mm, Pitch 0.4mm, IPC Medium Density)
footprint TQFP128_L (Thin QFP, 128-Leads, Body 14x14mm, Pitch 0.4mm, IPC High Density)
footprint TQFP128_M (Thin QFP, 128-Leads, Body 14x14mm, Pitch 0.4mm, IPC Low Density)
3D model 2096VL-TQFP128 (128-Pin Thin Quad Flat Pack 0.4 mm Pitch)
pins: 1 I/O85 (io), 2 VCC (power), 3 I/O86 (io), 4 I/O87 (io), 5 I/O88 (io), 6 I/O89 (io), 7 I/O90 (io), 8 I/O91 (io), 9 I/O92 (io), 10 I/O93 (io), 11 I/O94 (io), 12 I/O95 (io), 13 NC, 14 Y0 (in), 15 ~{RESE}T (in), 16 VCC (power), 17 GOE1 (in), 18 GND (power), 19 ~{BSCAN} (in), 20 TDI/IN0 (in), 21 I/O0 (io), 22 I/O1 (io), 23 I/O2 (io), 24 I/O3 (io), 25 I/O4 (io), 26 I/O5 (io), 27 I/O6 (io), 28 I/O7 (io), 29 I/O8 (io), 30 I/O9 (io), 31 VCC (power), 32 I/O10 (io), 33 I/O11 (io), 34 GND (power), 35 I/O12 (io), 36 I/O13 (io), 37 I/O14 (io), 38 I/O15 (io), 39 I/O16 (io), 40 I/O17 (io), 41 I/O18 (io), 42 I/O19 (io), 43 I/O20 (io), 44 I/O21 (io), 45 I/O22 (io), 46 I/O23 (io), 47 VCC (power), 48 TMS/IN1 (in), 49 NC, 50 GND (power), 51 I/O24 (io), 52 I/O25 (io), 53 I/O26 (io), 54 I/O27 (io), 55 I/O28 (io), 56 I/O29 (io), 57 I/O30 (io), 58 I/O31 (io), 59 I/O32 (io), 60 I/O33 (io), 61 I/O34 (io), 62 I/O35 (io), 63 GND (power), 64 I/O36 (io), 65 I/O37 (io), 66 VCC (power), 67 I/O38 (io), 68 I/O39 (io), 69 I/O40 (io), 70 I/O41 (io), 71 I/O42 (io), 72 I/O43 (io), 73 I/O44 (io), 74 I/O45 (io), 75 I/O46 (io), 76 I/O47 (io), 77 TCK/IN3 (in), 78 Y2 (in), 79 GND (power), 80 GOE0 (in), 81 VCC (power), 82 NC, 83 Y1 (in), 84 IN4 (in), 85 I/O48 (io), 86 I/O49 (io), 87 I/O50 (io), 88 I/O51 (io), 89 I/O52 (io), 90 I/O53 (io), 91 I/O54 (io), 92 I/O55 (io), 93 I/O56 (io), 94 I/O57 (io), 95 VCC (power), 96 I/O58 (io), 97 I/O59 (io), 98 GND (power), 99 I/O60 (io), 100 I/O61 (io), 101 I/O62 (io), 102 I/O63 (io), 103 I/O64 (io), 104 I/O65 (io), 105 I/O66 (io), 106 I/O67 (io), 107 I/O68 (io), 108 I/O69 (io), 109 I/O70 (io), 110 I/O71 (io), 111 GND (power), 112 TDO/IN2 (io), 113 IN5 (in), 114 VCC (power), 115 I/O72 (io), 116 I/O73 (io), 117 I/O74 (io), 118 I/O75 (io), 119 I/O76 (io), 120 I/O77 (io), 121 I/O78 (io), 122 I/O79 (io), 123 I/O80 (io), 124 I/O81 (io), 125 I/O82 (io), 126 I/O83 (io), 127 GND (power), 128 I/O84 (io)

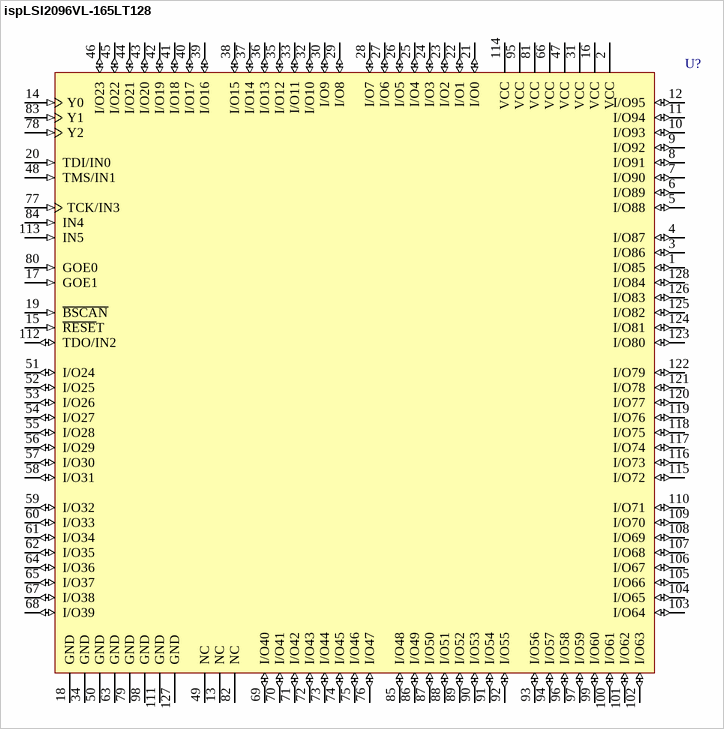
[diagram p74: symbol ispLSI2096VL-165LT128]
